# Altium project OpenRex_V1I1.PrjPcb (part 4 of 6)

## Sheet [07] - CPU - CSI, DISP.SchDoc
size A2; DocumentNumber: 7; SheetNumber: 7; SheetTotal: 31
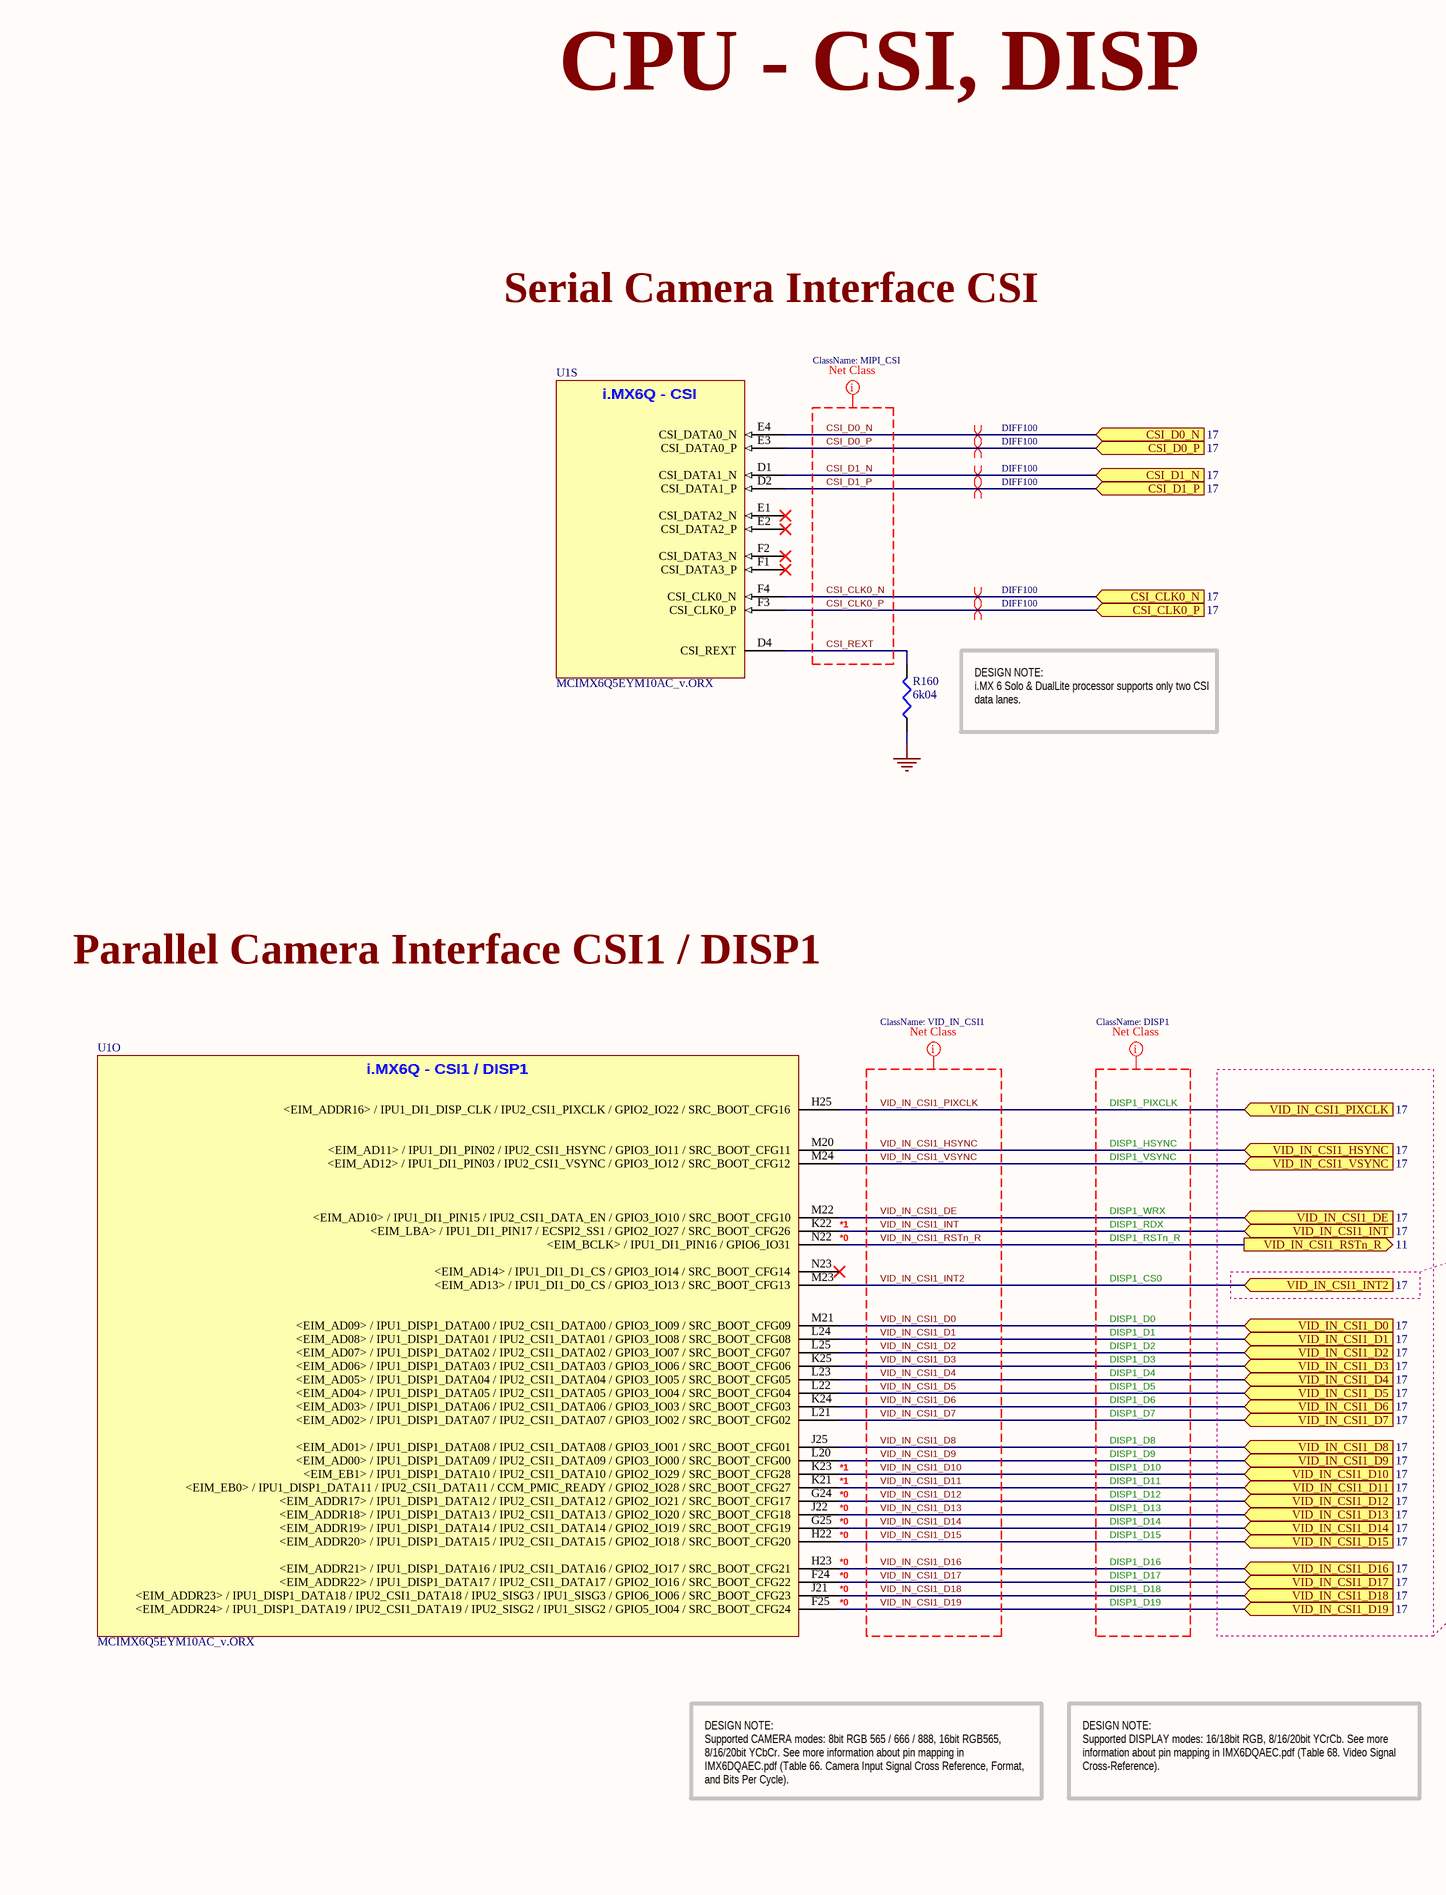
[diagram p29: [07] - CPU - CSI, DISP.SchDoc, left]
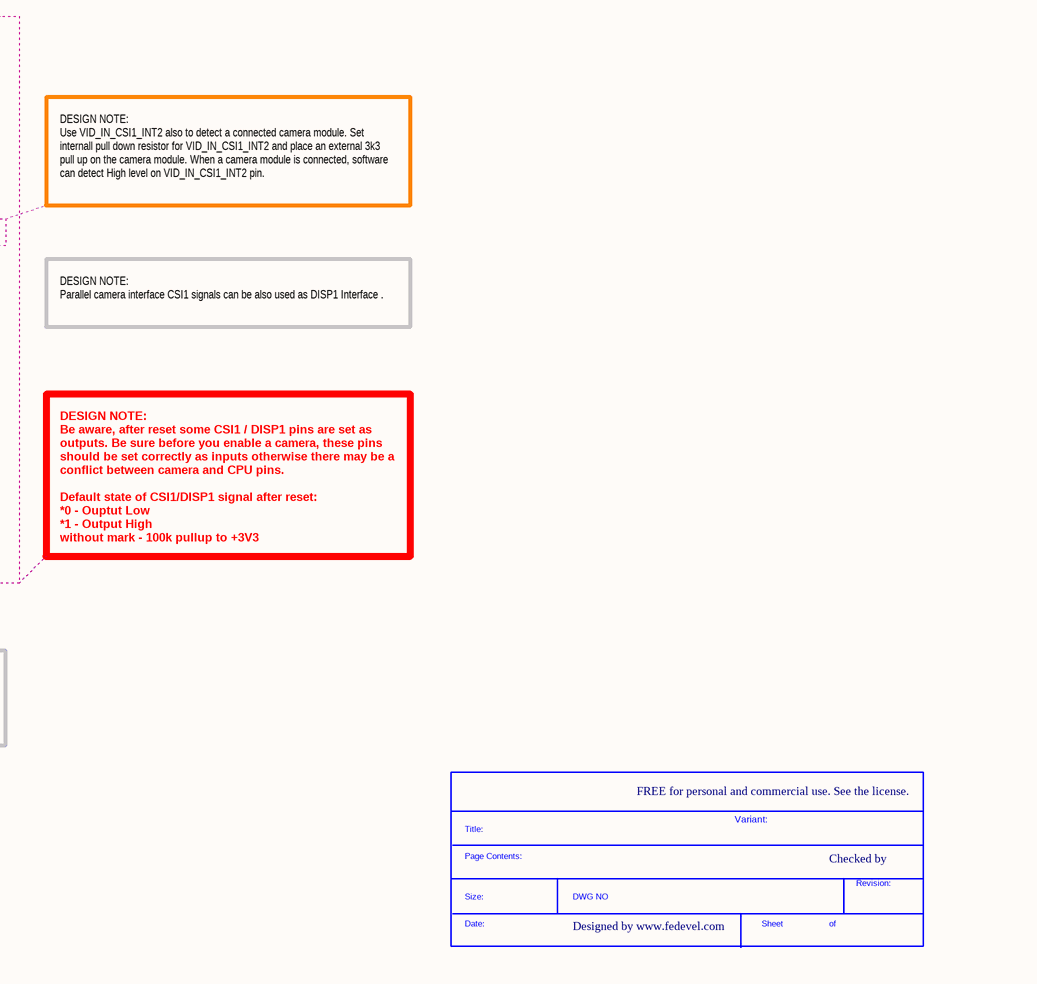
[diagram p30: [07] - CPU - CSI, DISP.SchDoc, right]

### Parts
(Parts that share a designator on the sheet are numbered #1, #2 ... from top to bottom, then left to right.)
*#18  SDTitleBlock  (value not drawn)  (graphical)
R160  6k04  [R0201]
U1  MCIMX6Q5EYM10AC_v.ORX  [PBGA624]  (parts O,S of 21)

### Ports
CSI_CLK0_N (in, see 17), CSI_CLK0_P (in, see 17), CSI_D0_N (in, see 17), CSI_D0_P (in, see 17), CSI_D1_N (in, see 17), CSI_D1_P (in, see 17), VID_IN_CSI1_D0 (in, see 17), VID_IN_CSI1_D1 (in, see 17), VID_IN_CSI1_D2 (in, see 17), VID_IN_CSI1_D3 (in, see 17), VID_IN_CSI1_D4 (in, see 17), VID_IN_CSI1_D5 (in, see 17), VID_IN_CSI1_D6 (in, see 17), VID_IN_CSI1_D7 (in, see 17), VID_IN_CSI1_D8 (in, see 17), VID_IN_CSI1_D9 (in, see 17), VID_IN_CSI1_D10 (in, see 17), VID_IN_CSI1_D11 (in, see 17), VID_IN_CSI1_D12 (in, see 17), VID_IN_CSI1_D13 (in, see 17), VID_IN_CSI1_D14 (in, see 17), VID_IN_CSI1_D15 (in, see 17), VID_IN_CSI1_D16 (in, see 17), VID_IN_CSI1_D17 (in, see 17), VID_IN_CSI1_D18 (in, see 17), VID_IN_CSI1_D19 (in, see 17), VID_IN_CSI1_DE (in, see 17), VID_IN_CSI1_HSYNC (in, see 17), VID_IN_CSI1_INT2 (in, see 17), VID_IN_CSI1_INT (in, see 17), VID_IN_CSI1_PIXCLK (in, see 17), VID_IN_CSI1_RSTn_R (out, see 11), VID_IN_CSI1_VSYNC (in, see 17)

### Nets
GND: R160.1
CSI_CLK0_N: U1.F4(CSI_CLK0_N) ; port CSI_CLK0_N
CSI_CLK0_P: U1.F3(CSI_CLK0_P) ; port CSI_CLK0_P
CSI_D0_N: U1.E4(CSI_DATA0_N) ; port CSI_D0_N
CSI_D0_P: U1.E3(CSI_DATA0_P) ; port CSI_D0_P
CSI_D1_N: U1.D1(CSI_DATA1_N) ; port CSI_D1_N
CSI_D1_P: U1.D2(CSI_DATA1_P) ; port CSI_D1_P
CSI_REXT: R160.2 U1.D4(CSI_REXT)
VID_IN_CSI1_D0: U1.M21(<EIM_AD09>_/_IPU1_DISP1_DATA00_/_IPU2_CSI1_DATA00_/_GPIO3_IO09_/_SRC_BOOT_CFG09) ; port VID_IN_CSI1_D0
VID_IN_CSI1_D1: U1.L24(<EIM_AD08>_/_IPU1_DISP1_DATA01_/_IPU2_CSI1_DATA01_/_GPIO3_IO08_/_SRC_BOOT_CFG08) ; port VID_IN_CSI1_D1
VID_IN_CSI1_D2: U1.L25(<EIM_AD07>_/_IPU1_DISP1_DATA02_/_IPU2_CSI1_DATA02_/_GPIO3_IO07_/_SRC_BOOT_CFG07) ; port VID_IN_CSI1_D2
VID_IN_CSI1_D3: U1.K25(<EIM_AD06>_/_IPU1_DISP1_DATA03_/_IPU2_CSI1_DATA03_/_GPIO3_IO06_/_SRC_BOOT_CFG06) ; port VID_IN_CSI1_D3
VID_IN_CSI1_D4: U1.L23(<EIM_AD05>_/_IPU1_DISP1_DATA04_/_IPU2_CSI1_DATA04_/_GPIO3_IO05_/_SRC_BOOT_CFG05) ; port VID_IN_CSI1_D4
VID_IN_CSI1_D5: U1.L22(<EIM_AD04>_/_IPU1_DISP1_DATA05_/_IPU2_CSI1_DATA05_/_GPIO3_IO04_/_SRC_BOOT_CFG04) ; port VID_IN_CSI1_D5
VID_IN_CSI1_D6: U1.K24(<EIM_AD03>_/_IPU1_DISP1_DATA06_/_IPU2_CSI1_DATA06_/_GPIO3_IO03_/_SRC_BOOT_CFG03) ; port VID_IN_CSI1_D6
VID_IN_CSI1_D7: U1.L21(<EIM_AD02>_/_IPU1_DISP1_DATA07_/_IPU2_CSI1_DATA07_/_GPIO3_IO02_/_SRC_BOOT_CFG02) ; port VID_IN_CSI1_D7
VID_IN_CSI1_D8: U1.J25(<EIM_AD01>_/_IPU1_DISP1_DATA08_/_IPU2_CSI1_DATA08_/_GPIO3_IO01_/_SRC_BOOT_CFG01) ; port VID_IN_CSI1_D8
VID_IN_CSI1_D9: U1.L20(<EIM_AD00>_/_IPU1_DISP1_DATA09_/_IPU2_CSI1_DATA09_/_GPIO3_IO00_/_SRC_BOOT_CFG00) ; port VID_IN_CSI1_D9
VID_IN_CSI1_D10: U1.K23(<EIM_EB1>_/_IPU1_DISP1_DATA10_/_IPU2_CSI1_DATA10_/_GPIO2_IO29_/_SRC_BOOT_CFG28) ; port VID_IN_CSI1_D10
VID_IN_CSI1_D11: U1.K21(<EIM_EB0>_/_IPU1_DISP1_DATA11_/_IPU2_CSI1_DATA11_/_CCM_PMIC_READY_/_GPIO2_IO28_/_SRC_BOOT_CFG27) ; port VID_IN_CSI1_D11
VID_IN_CSI1_D12: U1.G24(<EIM_ADDR17>_/_IPU1_DISP1_DATA12_/_IPU2_CSI1_DATA12_/_GPIO2_IO21_/_SRC_BOOT_CFG17) ; port VID_IN_CSI1_D12
VID_IN_CSI1_D13: U1.J22(<EIM_ADDR18>_/_IPU1_DISP1_DATA13_/_IPU2_CSI1_DATA13_/_GPIO2_IO20_/_SRC_BOOT_CFG18) ; port VID_IN_CSI1_D13
VID_IN_CSI1_D14: U1.G25(<EIM_ADDR19>_/_IPU1_DISP1_DATA14_/_IPU2_CSI1_DATA14_/_GPIO2_IO19_/_SRC_BOOT_CFG19) ; port VID_IN_CSI1_D14
VID_IN_CSI1_D15: U1.H22(<EIM_ADDR20>_/_IPU1_DISP1_DATA15_/_IPU2_CSI1_DATA15_/_GPIO2_IO18_/_SRC_BOOT_CFG20) ; port VID_IN_CSI1_D15
VID_IN_CSI1_D16: U1.H23(<EIM_ADDR21>_/_IPU1_DISP1_DATA16_/_IPU2_CSI1_DATA16_/_GPIO2_IO17_/_SRC_BOOT_CFG21) ; port VID_IN_CSI1_D16
VID_IN_CSI1_D17: U1.F24(<EIM_ADDR22>_/_IPU1_DISP1_DATA17_/_IPU2_CSI1_DATA17_/_GPIO2_IO16_/_SRC_BOOT_CFG22) ; port VID_IN_CSI1_D17
VID_IN_CSI1_D18: U1.J21(<EIM_ADDR23>_/_IPU1_DISP1_DATA18_/_IPU2_CSI1_DATA18_/_IPU2_SISG3_/_IPU1_SISG3_/_GPIO6_IO06_/_SRC_BOOT_CFG23) ; port VID_IN_CSI1_D18
VID_IN_CSI1_D19: U1.F25(<EIM_ADDR24>_/_IPU1_DISP1_DATA19_/_IPU2_CSI1_DATA19_/_IPU2_SISG2_/_IPU1_SISG2_/_GPIO5_IO04_/_SRC_BOOT_CFG24) ; port VID_IN_CSI1_D19
VID_IN_CSI1_DE: U1.M22(<EIM_AD10>_/_IPU1_DI1_PIN15_/_IPU2_CSI1_DATA_EN_/_GPIO3_IO10_/_SRC_BOOT_CFG10) ; port VID_IN_CSI1_DE
VID_IN_CSI1_HSYNC: U1.M20(<EIM_AD11>_/_IPU1_DI1_PIN02_/_IPU2_CSI1_HSYNC_/_GPIO3_IO11_/_SRC_BOOT_CFG11) ; port VID_IN_CSI1_HSYNC
VID_IN_CSI1_INT: U1.K22(<EIM_LBA>_/_IPU1_DI1_PIN17_/_ECSPI2_SS1_/_GPIO2_IO27_/_SRC_BOOT_CFG26) ; port VID_IN_CSI1_INT
VID_IN_CSI1_INT2: U1.M23(<EIM_AD13>_/_IPU1_DI1_D0_CS_/_GPIO3_IO13_/_SRC_BOOT_CFG13) ; port VID_IN_CSI1_INT2
VID_IN_CSI1_PIXCLK: U1.H25(<EIM_ADDR16>_/_IPU1_DI1_DISP_CLK_/_IPU2_CSI1_PIXCLK_/_GPIO2_IO22_/_SRC_BOOT_CFG16) ; port VID_IN_CSI1_PIXCLK
VID_IN_CSI1_RSTn_R: U1.N22(<EIM_BCLK>_/_IPU1_DI1_PIN16_/_GPIO6_IO31) ; port VID_IN_CSI1_RSTn_R
VID_IN_CSI1_VSYNC: U1.M24(<EIM_AD12>_/_IPU1_DI1_PIN03_/_IPU2_CSI1_VSYNC_/_GPIO3_IO12_/_SRC_BOOT_CFG12) ; port VID_IN_CSI1_VSYNC

Not connected (* = marked no-connect by the designer): U1 E1(CSI_DATA2_N)* E2(CSI_DATA2_P)* F1(CSI_DATA3_P)* F2(CSI_DATA3_N)* N23(<EIM_AD14>_/_IPU1_DI1_D1_CS_/_GPIO3_IO14_/_SRC_BOOT_CFG14)*

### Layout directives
net class DISP1: (no net found under the mark)
net class VID_IN_CSI1: VID_IN_CSI1_D0, VID_IN_CSI1_D1, VID_IN_CSI1_D2, VID_IN_CSI1_D3, VID_IN_CSI1_D4, VID_IN_CSI1_D5, VID_IN_CSI1_D6, VID_IN_CSI1_D7, VID_IN_CSI1_D8, VID_IN_CSI1_D9, VID_IN_CSI1_D10, VID_IN_CSI1_D11, VID_IN_CSI1_D12, VID_IN_CSI1_D13, VID_IN_CSI1_D14, VID_IN_CSI1_D15, VID_IN_CSI1_D16, VID_IN_CSI1_D17, VID_IN_CSI1_D18, VID_IN_CSI1_D19, VID_IN_CSI1_DE, VID_IN_CSI1_HSYNC, VID_IN_CSI1_INT, VID_IN_CSI1_INT2, VID_IN_CSI1_PIXCLK, VID_IN_CSI1_RSTn_R, VID_IN_CSI1_VSYNC
differential pair; net class DIFF100: CSI_CLK0_N, CSI_CLK0_P, CSI_D0_N, CSI_D0_P, CSI_D1_N, CSI_D1_P
net class MIPI_CSI: CSI_CLK0_N, CSI_CLK0_P, CSI_D0_N, CSI_D0_P, CSI_D1_N, CSI_D1_P, CSI_REXT

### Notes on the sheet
- CPU - CSI, DISP
- Serial Camera Interface CSI
- DESIGN NOTE:
  i.MX 6 Solo & DualLite processor supports only two CSI data lanes.
- Parallel Camera Interface CSI1 / DISP1
- DISP1_PIXCLK
- DISP1_HSYNC
- DISP1_VSYNC
- (near U1) *1
- (near U1) *0
- DISP1_RDX
- DISP1_WRX
- DISP1_RSTn_R
- DESIGN NOTE:
  Use VID_IN_CSI1_INT2 also to detect a connected camera module. Set internall pull down resistor for VID_IN_CSI1_INT2 and place an external 3k3 pull up on the camera module. When a camera module is connected, software can detect High level on VID_IN_CSI1_INT2 pin.
- DISP1_D0
- DISP1_CS0
- DISP1_D1
- DISP1_D2
- DISP1_D3
- DISP1_D4
- DISP1_D5
- DESIGN NOTE:
  Parallel camera interface CSI1 signals can be also used as DISP1 Interface .
- DISP1_D6
- DISP1_D7
- DISP1_D8
- DISP1_D9
- DISP1_D10
- DISP1_D11
- DISP1_D12
- DISP1_D13
- DISP1_D14
- DISP1_D15
- DISP1_D16
- DISP1_D17
- DISP1_D18
- DISP1_D19
- DESIGN NOTE:
  Be aware, after reset some CSI1 / DISP1 pins are set as outputs. Be sure before you enable a camera, these pins should be set correctly as inputs otherwise there may be a conflict between camera and CPU pins.
  Default state of CSI1/DISP1 signal after reset:
  *0 - Ouptut Low
  *1 - Output High
  without mark - 100k pullup to +3V3
- DESIGN NOTE:
  Supported CAMERA modes: 8bit RGB 565 / 666 / 888, 16bit RGB565, 8/16/20bit YCbCr. See more information about pin mapping in IMX6DQAEC.pdf (Table 66. Camera Input Signal Cross Reference, Format, and Bits Per Cycle).
- DESIGN NOTE:
  Supported DISPLAY modes: 16/18bit RGB, 8/16/20bit YCrCb. See more information about pin mapping in IMX6DQAEC.pdf (Table 68. Video Signal Cross-Reference).
- FREE for personal and commercial use. See the license.
- Variant:
- Checked by
- Designed by www.fedevel.com

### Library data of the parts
R160 = ERJ-1GEF6041C: RES 6.04K OHM 1/20W 1% 0201 SMD; Manufacturer: Panasonic Electronic Components; Power (Watts): 0.05W, 1/20W; Temperature Coefficient: ±200ppm/°C; .Creator: MM
U1 = MCIMX6Q5EYM10AC_v.ORX: IC MCU 32BIT ARM QUAD 624FCBGA; Manufacturer: Freescale Semiconductor; Core Processor: ARM® Cortex™-A9; Core Size: 32-Bit Quad-Core; Speed: 1.0GHz; Connectivity: CAN, EBI/EMI, ESAI, Ethernet, GPMI, I2C, MMC/SD, PCI, SATA, SPI, UART, USB, USB OTG; Peripherals: DMA, HDMI, I2S/SSI/AC97, MIPI CSI, MIMI DSI, MIPI HIS, PWM, WDT; Number of I /O: 224; Program Memory Type: External Program Memory; RAM Size: 256K x 8; Voltage - Supply (Vcc/Vdd): 0.925 V ~ 1.5 V; Oscillator Type: Internal; .Creator: MM; .Checked PCB: MM, checked by RF

## Sheet [14] - MCU.SchDoc
size A2; DocumentNumber: 14; SheetNumber: 14; SheetTotal: 31
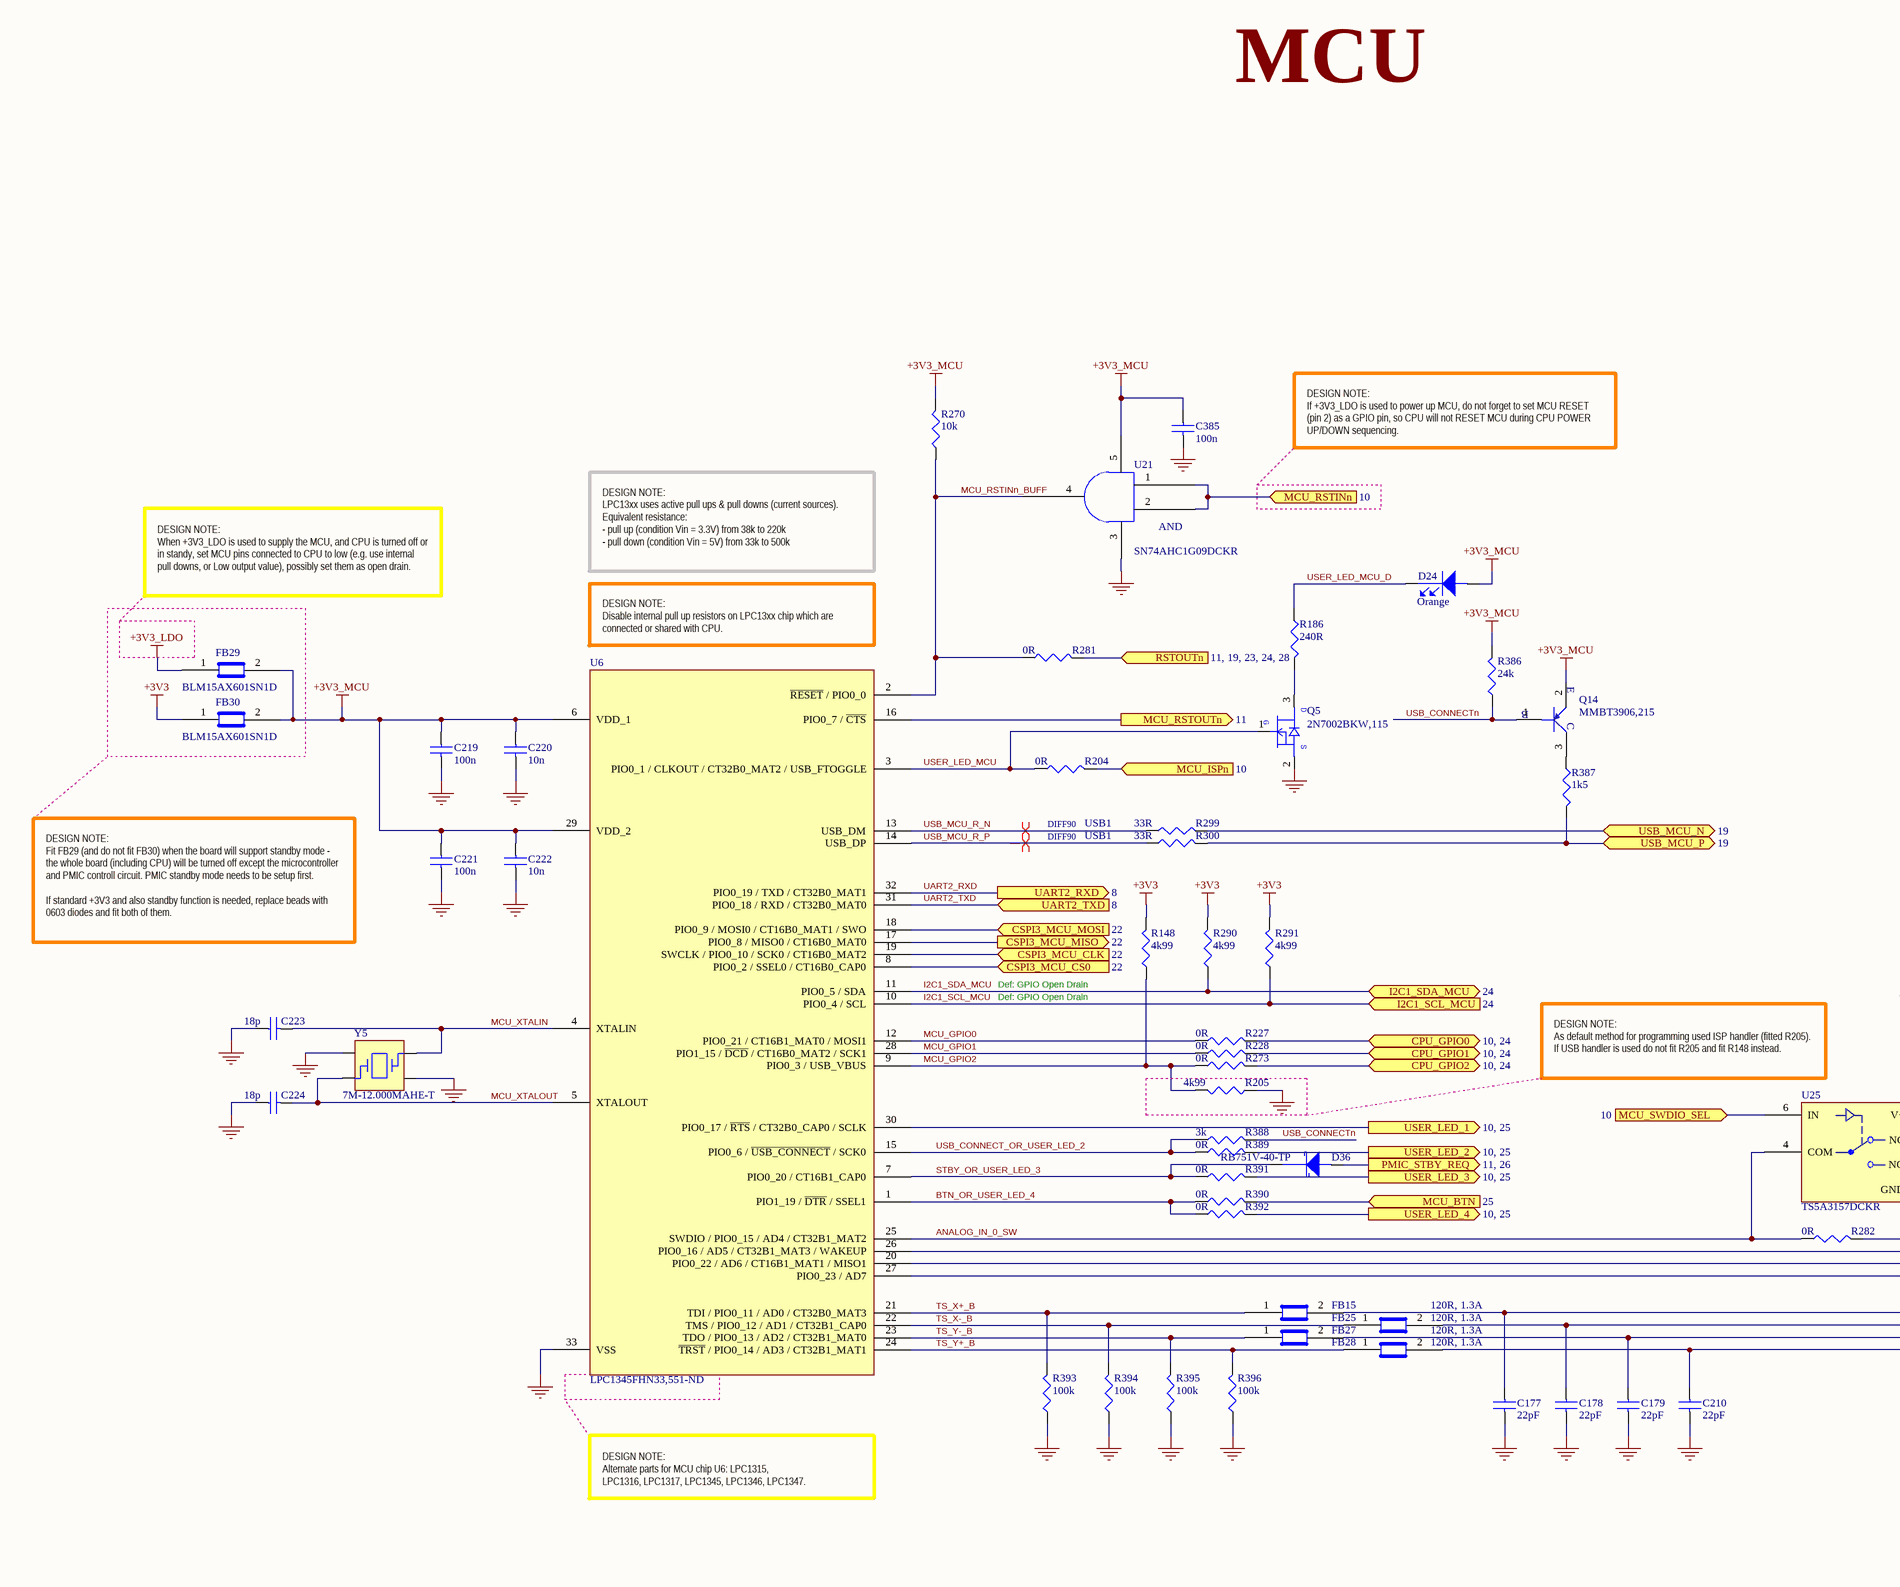
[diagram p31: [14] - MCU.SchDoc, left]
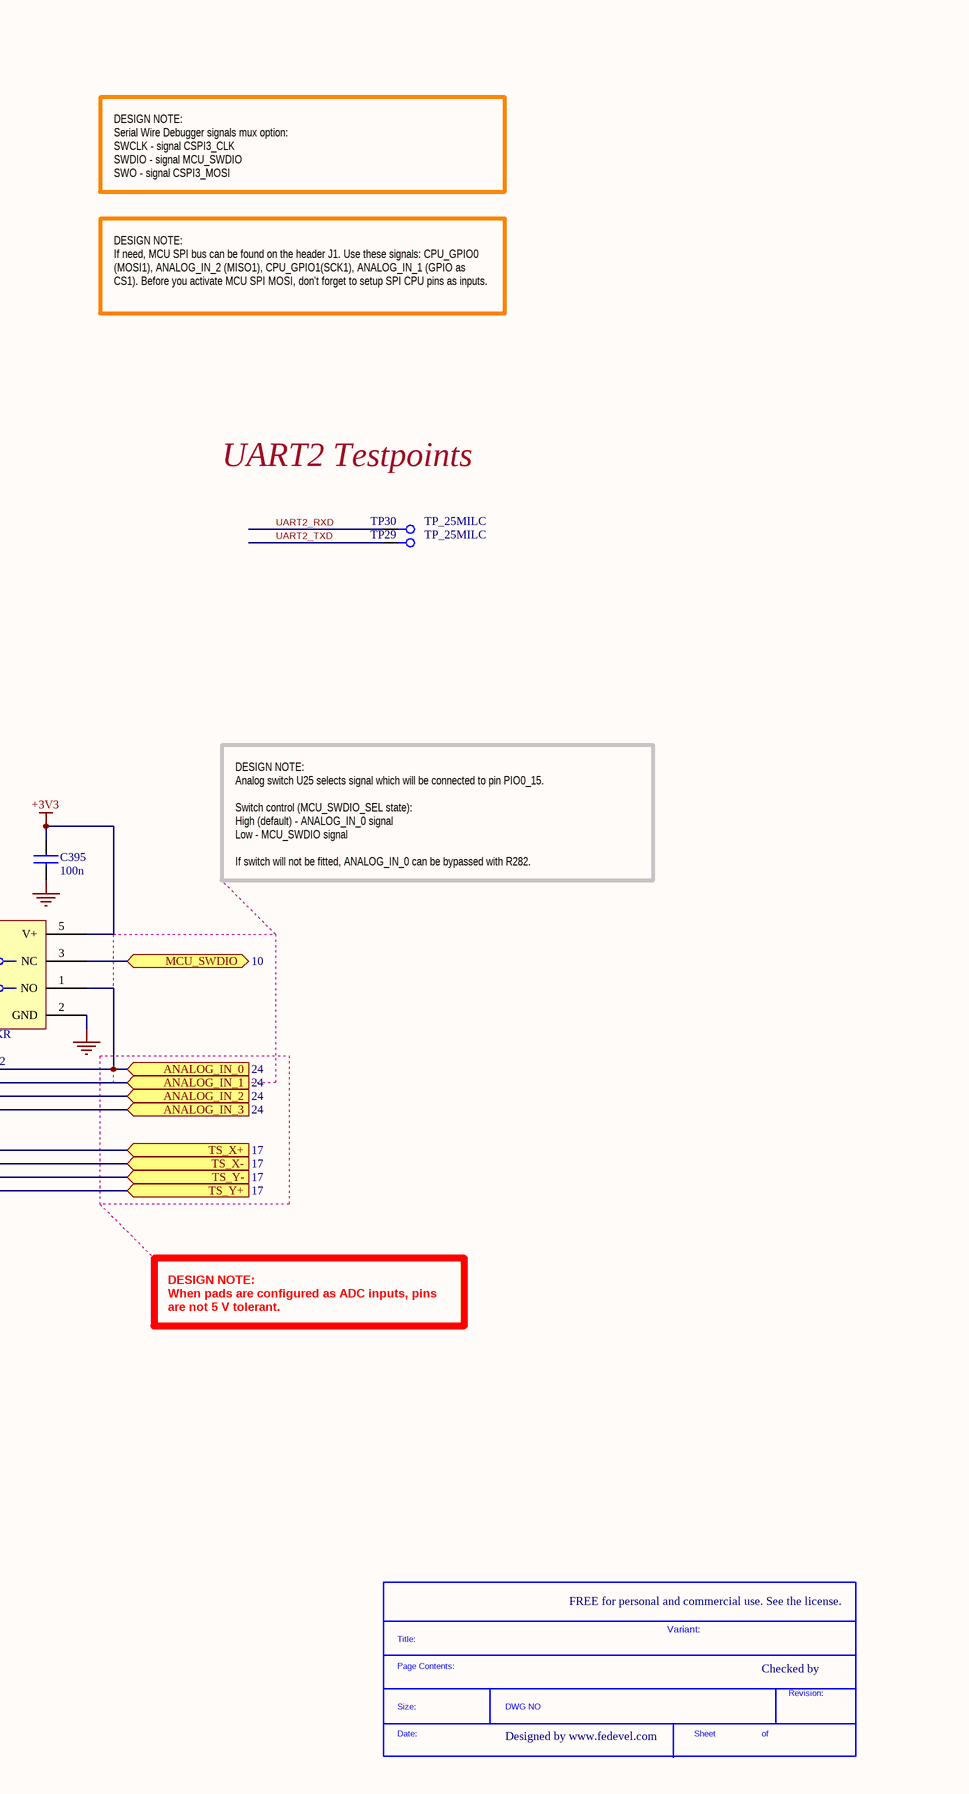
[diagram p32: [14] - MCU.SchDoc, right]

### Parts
(Parts that share a designator on the sheet are numbered #1, #2 ... from top to bottom, then left to right.)
*#19  SDTitleBlock  (value not drawn)  (graphical)
C177  22pF  [C0402]
C178  22pF  [C0402]
C179  22pF  [C0402]
C210  22pF  [C0402]
C219  100n  [C0402]
C220  10n  [C0402]
C221  100n  [C0402]
C222  10n  [C0402]
C223  18p  [C0402]
C224  18p  [C0402]
C385  100n  [C0402]
C395  100n  [C0402]
D24  Orange  [LED_0603]
D36  RB751V-40-TP  [SOD323]
FB15  120R, 1.3A  [C0402]
FB25  120R, 1.3A  [C0402]
FB27  120R, 1.3A  [C0402]
FB28  120R, 1.3A  [C0402]
FB29  BLM15AX601SN1D  [C0402]
FB30  BLM15AX601SN1D  [C0402]
Q5  2N7002BKW,115  [SC70_SOT323]
Q14  MMBT3906,215  [SOT-23-3-123]
R148  4k99  [R0402]
R186  240R  [R0402]
R204  0R  [R0402]
R205  4k99  [R0402]
R227  0R  [R0402]
R228  0R  [R0402]
R270  10k  [R0402]
R273  0R  [R0402]
R281  0R  [R0402]
R282  0R  [R0402]
R290  4k99  [R0402]
R291  4k99  [R0402]
R299  33R  [R0402]
R300  33R  [R0402]
R386  24k  [R0402]
R387  1k5  [R0402]
R388  3k  [R0402]
R389  0R  [R0402]
R390  0R  [R0402]
R391  0R  [R0402]
R392  0R  [R0402]
R393  100k  [R0402]
R394  100k  [R0402]
R395  100k  [R0402]
R396  100k  [R0402]
TP29  TP_25MILC  [TP_25C]  (no BOM)
TP30  TP_25MILC  [TP_25C]  (no BOM)
U6  LPC1345FHN33,551-ND  [HVQFN33_7x7mm]
U21  SN74AHC1G09DCKR  [SC70_5]
U25  TS5A3157DCKR  [SC70_6]
Y5  7M-12.000MAHE-T  [7M]

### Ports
ANALOG_IN_0 (in, see 24), ANALOG_IN_1 (in, see 24), ANALOG_IN_2 (in, see 24), ANALOG_IN_3 (in, see 24), CPU_GPIO0 (bidir, see 10, 24), CPU_GPIO1 (bidir, see 10, 24), CPU_GPIO2 (bidir, see 10, 24), CSPI3_MCU_CLK (in, see 22), CSPI3_MCU_CS0 (in, see 22), CSPI3_MCU_MISO (out, see 22), CSPI3_MCU_MOSI (in, see 22), I2C1_SCL_MCU (in, see 24), I2C1_SDA_MCU (bidir, see 24), MCU_BTN (in, see 25), MCU_ISPn (in, see 10), MCU_RSTINn (in, see 10), MCU_RSTOUTn (out, see 11), MCU_SWDIO (bidir, see 10), MCU_SWDIO_SEL (in, see 10), PMIC_STBY_REQ (out, see 11, 26), RSTOUTn (see 11, 19, 23, 24, 28), TS_X+ (in, see 17), TS_X- (in, see 17), TS_Y+ (in, see 17), TS_Y- (in, see 17), UART2_RXD (out, see 8), UART2_TXD (in, see 8), USB_MCU_N (bidir, see 19), USB_MCU_P (bidir, see 19), USER_LED_1 (out, see 10, 25), USER_LED_2 (out, see 10, 25), USER_LED_3 (out, see 10, 25), USER_LED_4 (out, see 10, 25)

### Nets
+3V3: C395.1 FB30.1 R148.2 R290.2 R291.2 U25.5(V+)
+3V3_LDO: FB29.1
+3V3_MCU: C219.1 C220.1 C221.1 C222.1 C385.1 D24.2(ANODE) FB29.2 FB30.2 Q14.2(E) R270.2 R386.2 U6.6(VDD_1) U6.29(VDD_2) U21.5(VCC)
GND: C177.2 C178.2 C179.2 C210.2 C219.2 C220.2 C221.2 C222.2 C223.1 C224.1 C385.2 C395.2 Q5.2(SOURCE) R205.1 R393.1 R394.1 R395.1 R396.1 U6.33(VSS) U21.3(GND) U25.2(GND) Y5.2 Y5.4
ANALOG_IN_0: R282.2 U25.1(NO) ; port ANALOG_IN_0
ANALOG_IN_0_SW: R282.1 U6.25(SWDIO_/_PIO0_15_/_AD4_/_CT32B1_MAT2) U25.4(COM)
ANALOG_IN_1: U6.26(PIO0_16_/_AD5_/_CT32B1_MAT3_/_WAKEUP) ; port ANALOG_IN_1
ANALOG_IN_2: U6.20(PIO0_22_/_AD6_/_CT16B1_MAT1_/_MISO1) ; port ANALOG_IN_2
ANALOG_IN_3: U6.27(PIO0_23_/_AD7) ; port ANALOG_IN_3
BTN_OR_USER_LED_4: R390.1 R392.1 U6.1(PIO1_19_/_~{DTR}_/_SSEL1)
CPU_GPIO0: R227.2 ; port CPU_GPIO0
CPU_GPIO1: R228.2 ; port CPU_GPIO1
CPU_GPIO2: R273.2 ; port CPU_GPIO2
CSPI3_MCU_CLK: U6.19(SWCLK_/_PIO0_10_/_SCK0_/_CT16B0_MAT2) ; port CSPI3_MCU_CLK
CSPI3_MCU_CS0: U6.8(PIO0_2_/_SSEL0_/_CT16B0_CAP0) ; port CSPI3_MCU_CS0
CSPI3_MCU_MISO: U6.17(PIO0_8_/_MISO0_/_CT16B0_MAT0) ; port CSPI3_MCU_MISO
CSPI3_MCU_MOSI: U6.18(PIO0_9_/_MOSI0_/_CT16B0_MAT1_/_SWO) ; port CSPI3_MCU_MOSI
I2C1_SCL_MCU: R291.1 U6.10(PIO0_4_/_SCL) ; port I2C1_SCL_MCU
I2C1_SDA_MCU: R290.1 U6.11(PIO0_5_/_SDA) ; port I2C1_SDA_MCU
MCU_BTN: R390.2 ; port MCU_BTN
MCU_GPIO0: R227.1 U6.12(PIO0_21_/_CT16B1_MAT0_/_MOSI1)
MCU_GPIO1: R228.1 U6.28(PIO1_15_/_~{DCD}_/_CT16B0_MAT2_/_SCK1)
MCU_GPIO2: R148.1 R205.2 R273.1 U6.9(PIO0_3_/_USB_VBUS)
MCU_ISPn: R204.2 ; port MCU_ISPn
MCU_RSTINn: U21.1(A) U21.2(B) ; port MCU_RSTINn
MCU_RSTINn_BUFF: R270.1 R281.1 U6.2(~{RESET}_/_PIO0_0) U21.4(Y)
MCU_RSTOUTn: U6.16(PIO0_7_/_~{CTS}) ; port MCU_RSTOUTn
MCU_SWDIO: U25.3(NC) ; port MCU_SWDIO
MCU_SWDIO_SEL: U25.6(IN) ; port MCU_SWDIO_SEL
MCU_XTALIN: C223.2 U6.4(XTALIN) Y5.1
MCU_XTALOUT: C224.2 U6.5(XTALOUT) Y5.3
PMIC_STBY_REQ: D36.2(ANODE) ; port PMIC_STBY_REQ
RSTOUTn: R281.2 ; port RSTOUTn
STBY_OR_USER_LED_3: D36.1(cathode) R391.1 U6.7(PIO0_20_/_CT16B1_CAP0)
TS_X+: C177.1 FB15.2 ; port TS_X+
TS_X+_B: FB15.1 R393.2 U6.21(TDI_/_PIO0_11_/_AD0_/_CT32B0_MAT3)
TS_X-: C178.1 FB25.2 ; port TS_X-
TS_X-_B: FB25.1 R394.2 U6.22(TMS_/_PIO0_12_/_AD1_/_CT32B1_CAP0)
TS_Y+: C210.1 FB28.2 ; port TS_Y+
TS_Y+_B: FB28.1 R396.2 U6.24(~{TRST}_/_PIO0_14_/_AD3_/_CT32B1_MAT1)
TS_Y-: C179.1 FB27.2 ; port TS_Y-
TS_Y-_B: FB27.1 R395.2 U6.23(TDO_/_PIO0_13_/_AD2_/_CT32B1_MAT0)
UART2_RXD: TP30.1 U6.32(PIO0_19_/_TXD_/_CT32B0_MAT1) ; port UART2_RXD
UART2_TXD: TP29.1 U6.31(PIO0_18_/_RXD_/_CT32B0_MAT0) ; port UART2_TXD
USB_CONNECT_OR_USER_LED_2: R388.1 R389.1 U6.15(PIO0_6_/_~{USB_CONNECT}_/_SCK0)
USB_CONNECTn: Q14.1(B) R386.1 R388.2
USB_MCU_N: R299.2 ; port USB_MCU_N
USB_MCU_P: R300.2 R387.2 ; port USB_MCU_P
USB_MCU_R_N: R299.1 U6.13(USB_DM)
USB_MCU_R_P: R300.1 U6.14(USB_DP)
USER_LED_1: U6.30(PIO0_17_/_~{RTS}_/_CT32B0_CAP0_/_SCLK) ; port USER_LED_1
USER_LED_2: R389.2 ; port USER_LED_2
USER_LED_3: R391.2 ; port USER_LED_3
USER_LED_4: R392.2 ; port USER_LED_4
USER_LED_MCU: Q5.1(GATE) R204.1 U6.3(PIO0_1_/_CLKOUT_/_CT32B0_MAT2_/_USB_FTOGGLE)
USER_LED_MCU_D: D24.1(cathode) R186.1
NetQ5_3: Q5.3(DRAIN) R186.2
NetQ14_3: Q14.3(C) R387.1

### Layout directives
differential pair; net class DIFF90; net class USB1: USB_MCU_R_N, USB_MCU_R_P

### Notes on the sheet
- MCU
- DESIGN NOTE:
  If +3V3_LDO is used to power up MCU, do not forget to set MCU RESET (pin 2) as a GPIO pin, so CPU will not RESET MCU during CPU POWER UP/DOWN sequencing.
- DESIGN NOTE:
  Serial Wire Debugger signals mux option:
  SWCLK - signal CSPI3_CLK
  SWDIO - signal MCU_SWDIO
  SWO - signal CSPI3_MOSI
- DESIGN NOTE:
  LPC13xx uses active pull ups & pull downs (current sources).
  Equivalent resistance:
  - pull up (condition Vin = 3.3V) from 38k to 220k
  - pull down (condition Vin = 5V) from 33k to 500k
- DESIGN NOTE:
  If need, MCU SPI bus can be found on the header J1. Use these signals: CPU_GPIO0 (MOSI1), ANALOG_IN_2 (MISO1), CPU_GPIO1(SCK1), ANALOG_IN_1 (GPIO as CS1). Before you activate MCU SPI MOSI, don't forget to setup SPI CPU pins as inputs.
- DESIGN NOTE:
  When +3V3_LDO is used to supply the MCU, and CPU is turned off or in standy, set MCU pins connected to CPU to low (e.g. use internal pull downs, or Low output value), possibly set them as open drain.
- DESIGN NOTE:
  Disable internal pull up resistors on LPC13xx chip which are connected or shared with CPU.
- UART2 Testpoints
- DESIGN NOTE:
  Fit FB29 (and do not fit FB30) when the board will support standby mode - the whole board (including CPU) will be turned off except the microcontroller and PMIC controll circuit. PMIC standby mode needs to be setup first.
  If standard +3V3 and also standby function is needed, replace beads with 0603 diodes and fit both of them.
- Def: GPIO Open Drain
- DESIGN NOTE:
  Analog switch U25 selects signal which will be connected to pin PIO0_15.
  Switch control (MCU_SWDIO_SEL state):
  High (default) - ANALOG_IN_0 signal
  Low - MCU_SWDIO signal
  If switch will not be fitted, ANALOG_IN_0 can be bypassed with R282.
- (near U25) DESIGN NOTE:
  As default method for programming used ISP handler (fitted R205). If USB handler is used do not fit R205 and fit R148 instead.
- DESIGN NOTE:
  Alternate parts for MCU chip U6: LPC1315,
  LPC1316, LPC1317, LPC1345, LPC1346, LPC1347.
- DESIGN NOTE:
  When pads are configured as ADC inputs, pins are not 5 V tolerant.
- FREE for personal and commercial use. See the license.
- Variant:
- Checked by
- Designed by www.fedevel.com

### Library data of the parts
C177-C179 C210 = C1005C0G1H220J: CAP CER 22PF 50V C0G 5% 0402; Manufacturer: TDK Corporation; .Checked PCB: used; Temperature Coefficient: C0G, NP0
C219 C221 C385 C395 = C1005X5R1H104K: CAP CER .10UF 50V X5R 10% 0402; Manufacturer: TDK Corporation; Capacitance: 0.1µF; Value: 100nF; .Checked PCB: used
C220 C222 = C1005X7R1H103K: CAP CER 10000PF 50V 10% X7R 0402; Manufacturer: TDK Corporation; Value: 10nF; .Checked PCB: used
C223 C224 = C1005C0G1H180J: CAP CER 18PF 50V C0G 5% 0402; Manufacturer: TDK Corporation; .Checked PCB: used; Temperature Coefficient: C0G, NP0
D24 = LO L29K-H2K1-24-Z: LED SMARTLED ORANGE 606NM 0603; Manufacturer: OSRAM Opto Semiconductors Inc; Millicandela Rating: 6.3mcd; Voltage - Forward (Vf) Typ: 1.8V; Current - Test: 2mA; Wavelength - Peak: 610nm; Viewing Angle: 160°; Lens Type: Diffused; Lens Style/Size: Rectangle with Flat Top, 1.3mm x 0.8mm; Luminous Flux @ Current - Test: 25 mlm; .Checked PCB: used
D36 = RB751V-40-TP: DIODE SCHTKY 30MA 30V SOD-323; Manufacturer: Micro Commercial Co; Diode Type: Schottky; Voltage - Forward (Vf) (Max) @ If: 370mV @ 1mA; Speed: Small Signal =< 200mA (Io), Any Speed; Current - Reverse Leakage @ Vr: 500nA @ 30V; Capacitance @ Vr, F: 2pF @ 1V, 1MHz; .Checked PCB: used
FB15 FB25 FB27 FB28 = BLM15PD121SN1D: FERRITE CHIP 120 OHM 1300MA 0402; Manufacturer: Murata Electronics North America; Impedance @ Frequency: 120 Ohm @ 100MHz; DC Resistance (DCR): 90 mOhm Max; Filter Type: Differential Mode - Single; .Checked PCB: MM
FB29 FB30 = BLM15AX601SN1D: FERRITE CHIP 600 OHM 0402 420mA; Manufacturer: Murata Electronics North America; .Checked PCB: used; Impedance @ Frequency: 600 Ohm @ 100MHz; DC Resistance (DCR): 340 mOhm Max; Filter Type: Differential Mode - Single; Number of Lines: 1
Q5 = 2N7002BKW,115: MOSFET N-CH 60V 310MA SOT323; Manufacturer: NXP Semiconductors; FET Type: MOSFET N-Channel, Metal Oxide; FET Feature: Logic Level Gate; Rds On (Max) @ Id, Vgs: 1.6 Ohm @ 500mA, 10V; Vgs(th) (Max) @ Id: 2.1V @ 250µA; Gate Charge (Qg) @ Vgs: 0.6nC @ 4.5V; Input Capacitance (Ciss) @ Vds: 50pF @ 10V; Power - Max: 275mW; .Checked PCB: used
Q14 = MMBT3906,215: TRANS PNP 40V 0.2A SOT23; Manufacturer: NXP Semiconductors; Current - Collector (Ic) (Max): 200mA; Vce Saturation (Max) @ Ib, Ic: 400mV @ 5mA, 50mA; DC Current Gain (hFE) (Min) @ Ic, Vce: 100 @ 10mA, 1V; Power - Max: 250mW; Frequency - Transition: 250MHz; .Checked PCB: MM
R148 R205 R290 R291 = RMCF0402FT4K99: RES TF 4.99K OHM 1% 1/16W 0402; Manufacturer: Stackpole Electronics Inc; Power (Watts): 0.063W, 1/16W; .Checked PCB: used; Temperature Coefficient: ±100ppm/°C
R186 = RMCF0402FT240R: RES TF 240 OHM 1% 0.0625W 0402; Manufacturer: Stackpole Electronics Inc; Resistance (Ohms): 240; Power (Watts): 0.063W, 1/16W; .Checked PCB: used; Temperature Coefficient: ±100ppm/°C
R204 R227 R228 R273 R281 R282 R389-R392 = RC0402JR-070RL: RES 0.0 OHM 1/16W 0402 SMD; Manufacturer: Yageo; Resistance (Ohms): 0.0; Power (Watts): 0.063W, 1/16W; Tolerance: Jumper; .Checked PCB: used
R270 = RC0402FR-0710KL: RES 10.0K OHM 1/16W 1% 0402 SMD; Manufacturer: Yageo; Power (Watts): 0.063W, 1/16W; .Checked PCB: used; Temperature Coefficient: ±100ppm/°C
R299 R300 = RMCF0402FT33R0: RES TF 33 OHM 1% 1/16W 0402; Manufacturer: Stackpole Electronics Inc; Resistance (Ohms): 33; Power (Watts): 0.063W, 1/16W; .Checked PCB: used; Temperature Coefficient: ±100ppm/°C
R386 = RC0402FR-0724KL: RES SMD 24K OHM 1% 1/16W 0402; Manufacturer: Yageo; Power (Watts): 0.063W, 1/16W; Temperature Coefficient: ±100ppm/°C; .Creator: MM
R387 = RC0402FR-071K5L: RES 1.50K OHM 1/16W 1% 0402 SMD; Manufacturer: Yageo; Resistance (Ohms): 1.5k; Power (Watts): 0.063W, 1/16W; Temperature Coefficient: ±100ppm/°C; .Creator: MM
R388 = RC0402FR-073KL: RES 3K OHM 1/16W 1% 0402 SMD; Manufacturer: Yageo; Power (Watts): 0.063W, 1/16W; Temperature Coefficient: ±100ppm/°C; .Creator: MM; .Checked SCH: used
R393-R396 = RMCF0402FT100K: RES 100K OHM 1/16W 1% 0402 SMD; Manufacturer: Stackpole Electronics Inc; Power (Watts): 0.063W, 1/16W; .Checked PCB: used; Temperature Coefficient: ±100ppm/°C
TP29 TP30 = TP_25MILC: Test Point 25mil
U6 = LPC1345FHN33,551: IC MCU ARM 32KB FLASH 32HVQFN; Manufacturer: NXP Semiconductors; Core Processor: ARM® Cortex®-M3; Core Size: 32-Bit; Speed: 72MHz; Connectivity: I²C, Microwire, SPI, SSI, SSP, UART/USART, USB; Peripherals: Brown-out Detect/Reset, POR, WDT; Number of I/O: 26; Program Memory Size: 32KB (32K x 8); EEPROM Size: 2K x 8; RAM Size: 10K x 8; Voltage - Supply (Vcc/Vdd): 2 V ~ 3.6 V; Data Converters: A/D 8x12b; Oscillator Type: Internal; .Checked PCB: MM
U21 = SN74AHC1G09DCKR: IC GATE AND 1CH 2-INP SC-70-5; Manufacturer: Texas Instruments; Logic Type: AND Gate; Number of Circuits: 1; Number of Inputs: 2; Voltage - Supply: 2 V ~ 5.5 V; Current - Quiescent (Max): 1µA; Current - Output High, Low: -, 8mA; Logic Level - Low: 0.5 V ~ 1.65 V; Logic Level - High: 1.5 V ~ 3.85 V; Max Propagation Delay @ V, Max CL: 7.5ns @ 5V, 50pF; .Creator: MM; .Checked PCB: RF, used by MM
U25 = TS5A3157DCKR: IC SWITCH SPDT SC70-6; Manufacturer: Texas Instruments; Circuit: 1 x SPDT; On-State Resistance: 10 Ohm; Voltage Supply Source: Single Supply; Voltage - Supply, Single/Dual (±): 1.65 V ~ 5.5 V; Current - Supply: 2.5µA; .Checked PCB: MM
Y5 = 7M-12.000MAHE-T: CRYSTAL 12MHZ 12PF SMD; Manufacturer: TXC CORPORATION; Frequency Stability: ±30ppm; ESR (Equivalent Series Resistance): 100 Ohm; Operating Mode: Fundamental; .Creator: MM

## Sheet [20] - ETHERNET, SATA.SchDoc
size A3; DocumentNumber: 20; SheetNumber: 20; SheetTotal: 31
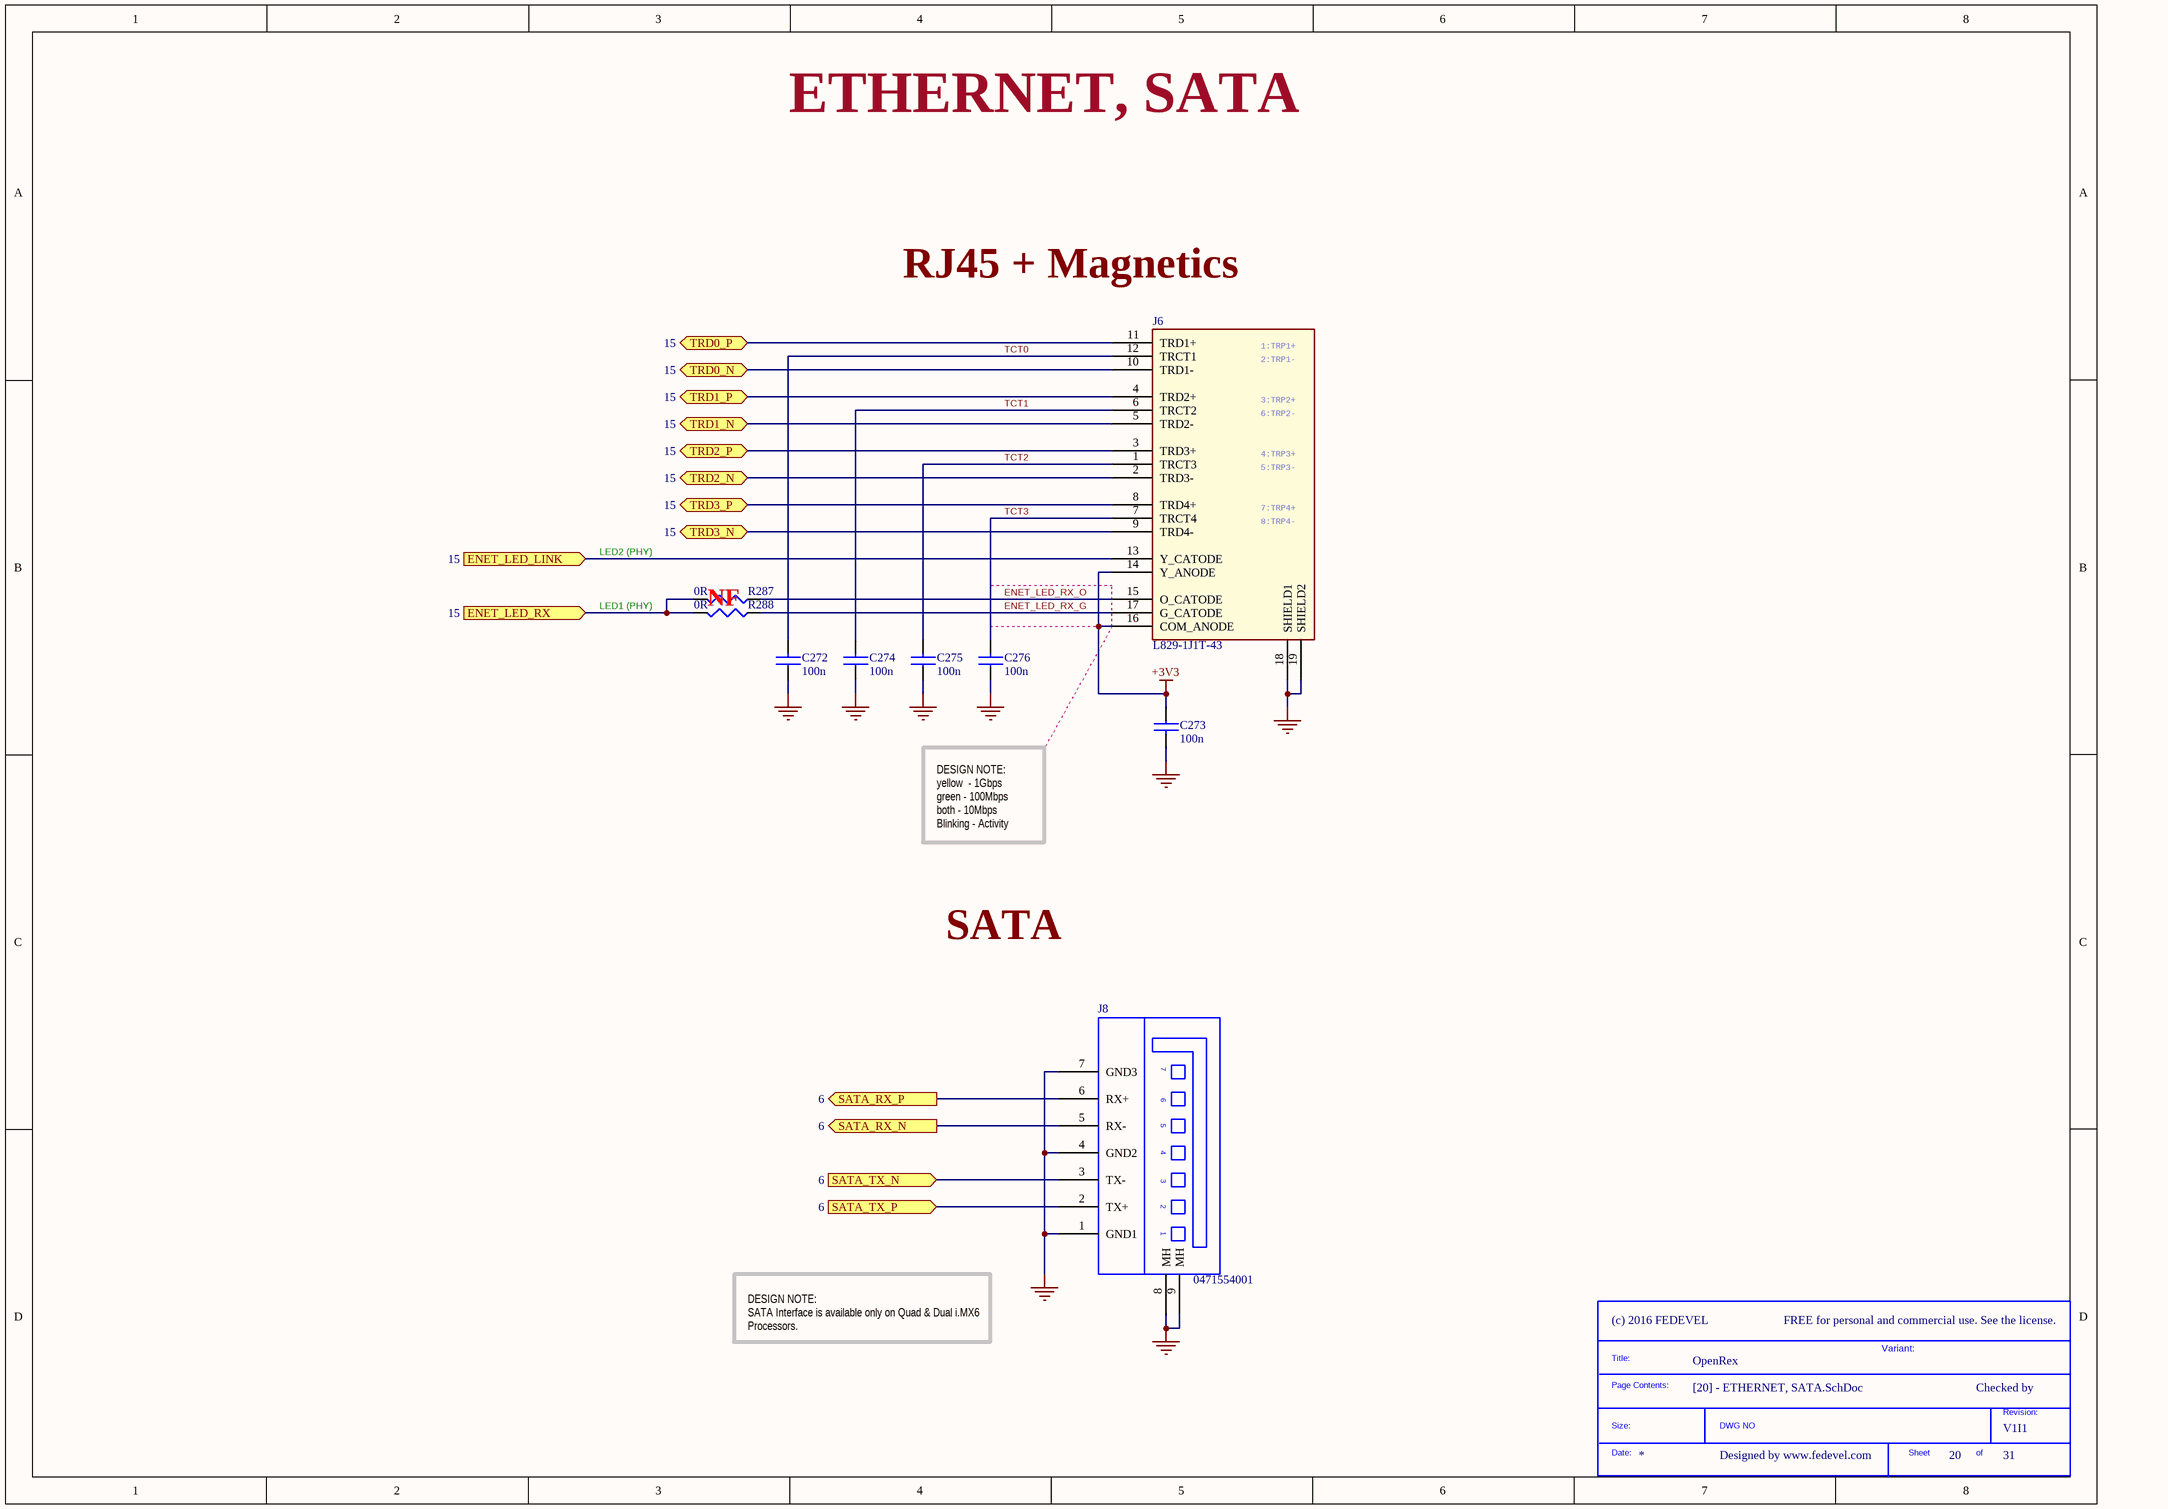
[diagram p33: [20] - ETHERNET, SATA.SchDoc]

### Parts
(Parts that share a designator on the sheet are numbered #1, #2 ... from top to bottom, then left to right.)
*#20  SDTitleBlock  (value not drawn)  (graphical)
C272  100n  [C0402]
C273  100n  [C0402]
C274  100n  [C0402]
C275  100n  [C0402]
C276  100n  [C0402]
J6  L829-1J1T-43  [L829-1J1T-43]
J8  0471554001  [SATA_VERTICAL]
R287  0R  [R0402]
R288  0R  [R0402]

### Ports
ENET_LED_LINK (in, see 15), ENET_LED_RX (in, see 15), SATA_RX_N (out, see 6), SATA_RX_P (out, see 6), SATA_TX_N (in, see 6), SATA_TX_P (in, see 6), TRD0_N (bidir, see 15), TRD0_P (bidir, see 15), TRD1_N (bidir, see 15), TRD1_P (bidir, see 15), TRD2_N (bidir, see 15), TRD2_P (bidir, see 15), TRD3_N (bidir, see 15), TRD3_P (bidir, see 15)

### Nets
+3V3: C273.1 J6.14(Y_ANODE) J6.16(COM_ANODE)
GND: C272.1 C273.2 C274.1 C275.1 C276.1 J6.18(SHIELD1) J6.19(SHIELD2) J8.1(GND1) J8.4(GND2) J8.7(GND3) J8.8(MH) J8.9(MH)
ENET_LED_LINK: J6.13(Y_CATODE) ; port ENET_LED_LINK
ENET_LED_RX: R287.2 R288.2 ; port ENET_LED_RX
ENET_LED_RX_G: J6.17(G_CATODE) R288.1
ENET_LED_RX_O: J6.15(O_CATODE) R287.1
SATA_RX_N: J8.5(RX-) ; port SATA_RX_N
SATA_RX_P: J8.6(RX+) ; port SATA_RX_P
SATA_TX_N: J8.3(TX-) ; port SATA_TX_N
SATA_TX_P: J8.2(TX+) ; port SATA_TX_P
TCT0: C272.2 J6.12(TRCT1)
TCT1: C274.2 J6.6(TRCT2)
TCT2: C275.2 J6.1(TRCT3)
TCT3: C276.2 J6.7(TRCT4)
TRD0_N: J6.10(TRD1-) ; port TRD0_N
TRD0_P: J6.11(TRD1+) ; port TRD0_P
TRD1_N: J6.5(TRD2-) ; port TRD1_N
TRD1_P: J6.4(TRD2+) ; port TRD1_P
TRD2_N: J6.2(TRD3-) ; port TRD2_N
TRD2_P: J6.3(TRD3+) ; port TRD2_P
TRD3_N: J6.9(TRD4-) ; port TRD3_N
TRD3_P: J6.8(TRD4+) ; port TRD3_P

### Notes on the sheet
- ETHERNET, SATA
- RJ45 + Magnetics
- LED2 (PHY)
- LED1 (PHY)
- DESIGN NOTE:
  yellow  - 1Gbps
  green - 100Mbps
  both - 10Mbps
  Blinking - Activity
- SATA
- FREE for personal and commercial use. See the license.
- DESIGN NOTE:
  SATA Interface is available only on Quad & Dual i.MX6 Processors.
- Variant:
- Checked by
- Designed by www.fedevel.com

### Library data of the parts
C272-C276 = C1005X5R1H104K: as C219 on sheet [14] - MCU
J6 = L829-1J1T-43: CONN MAGJACK 1PORT SHLD 1000BT; Manufacturer: Bel Fuse Inc; Connector Type: RJ45; Number of Ports: 1; Speed: 10/100/1000 Base-T; LED Color: Green, Orange - Yellow; Number of Cores per Jack: 8; Shielding: Shielded; Tab Direction: Up; .Checked PCB: RF
J8 = 0471554001: CONN SATA HDR 7POS PCB VERT; Manufacturer: Molex Inc; Connector Style: Header, Shrouded; Number of Positions: 7; .Checked PCB: used
R287 R288 = RC0402JR-070RL: as R204 on sheet [14] - MCU

## Sheet [25] - LEDS, BUTTONS.SchDoc
size A2; DocumentNumber: 25; SheetNumber: 25; SheetTotal: 31
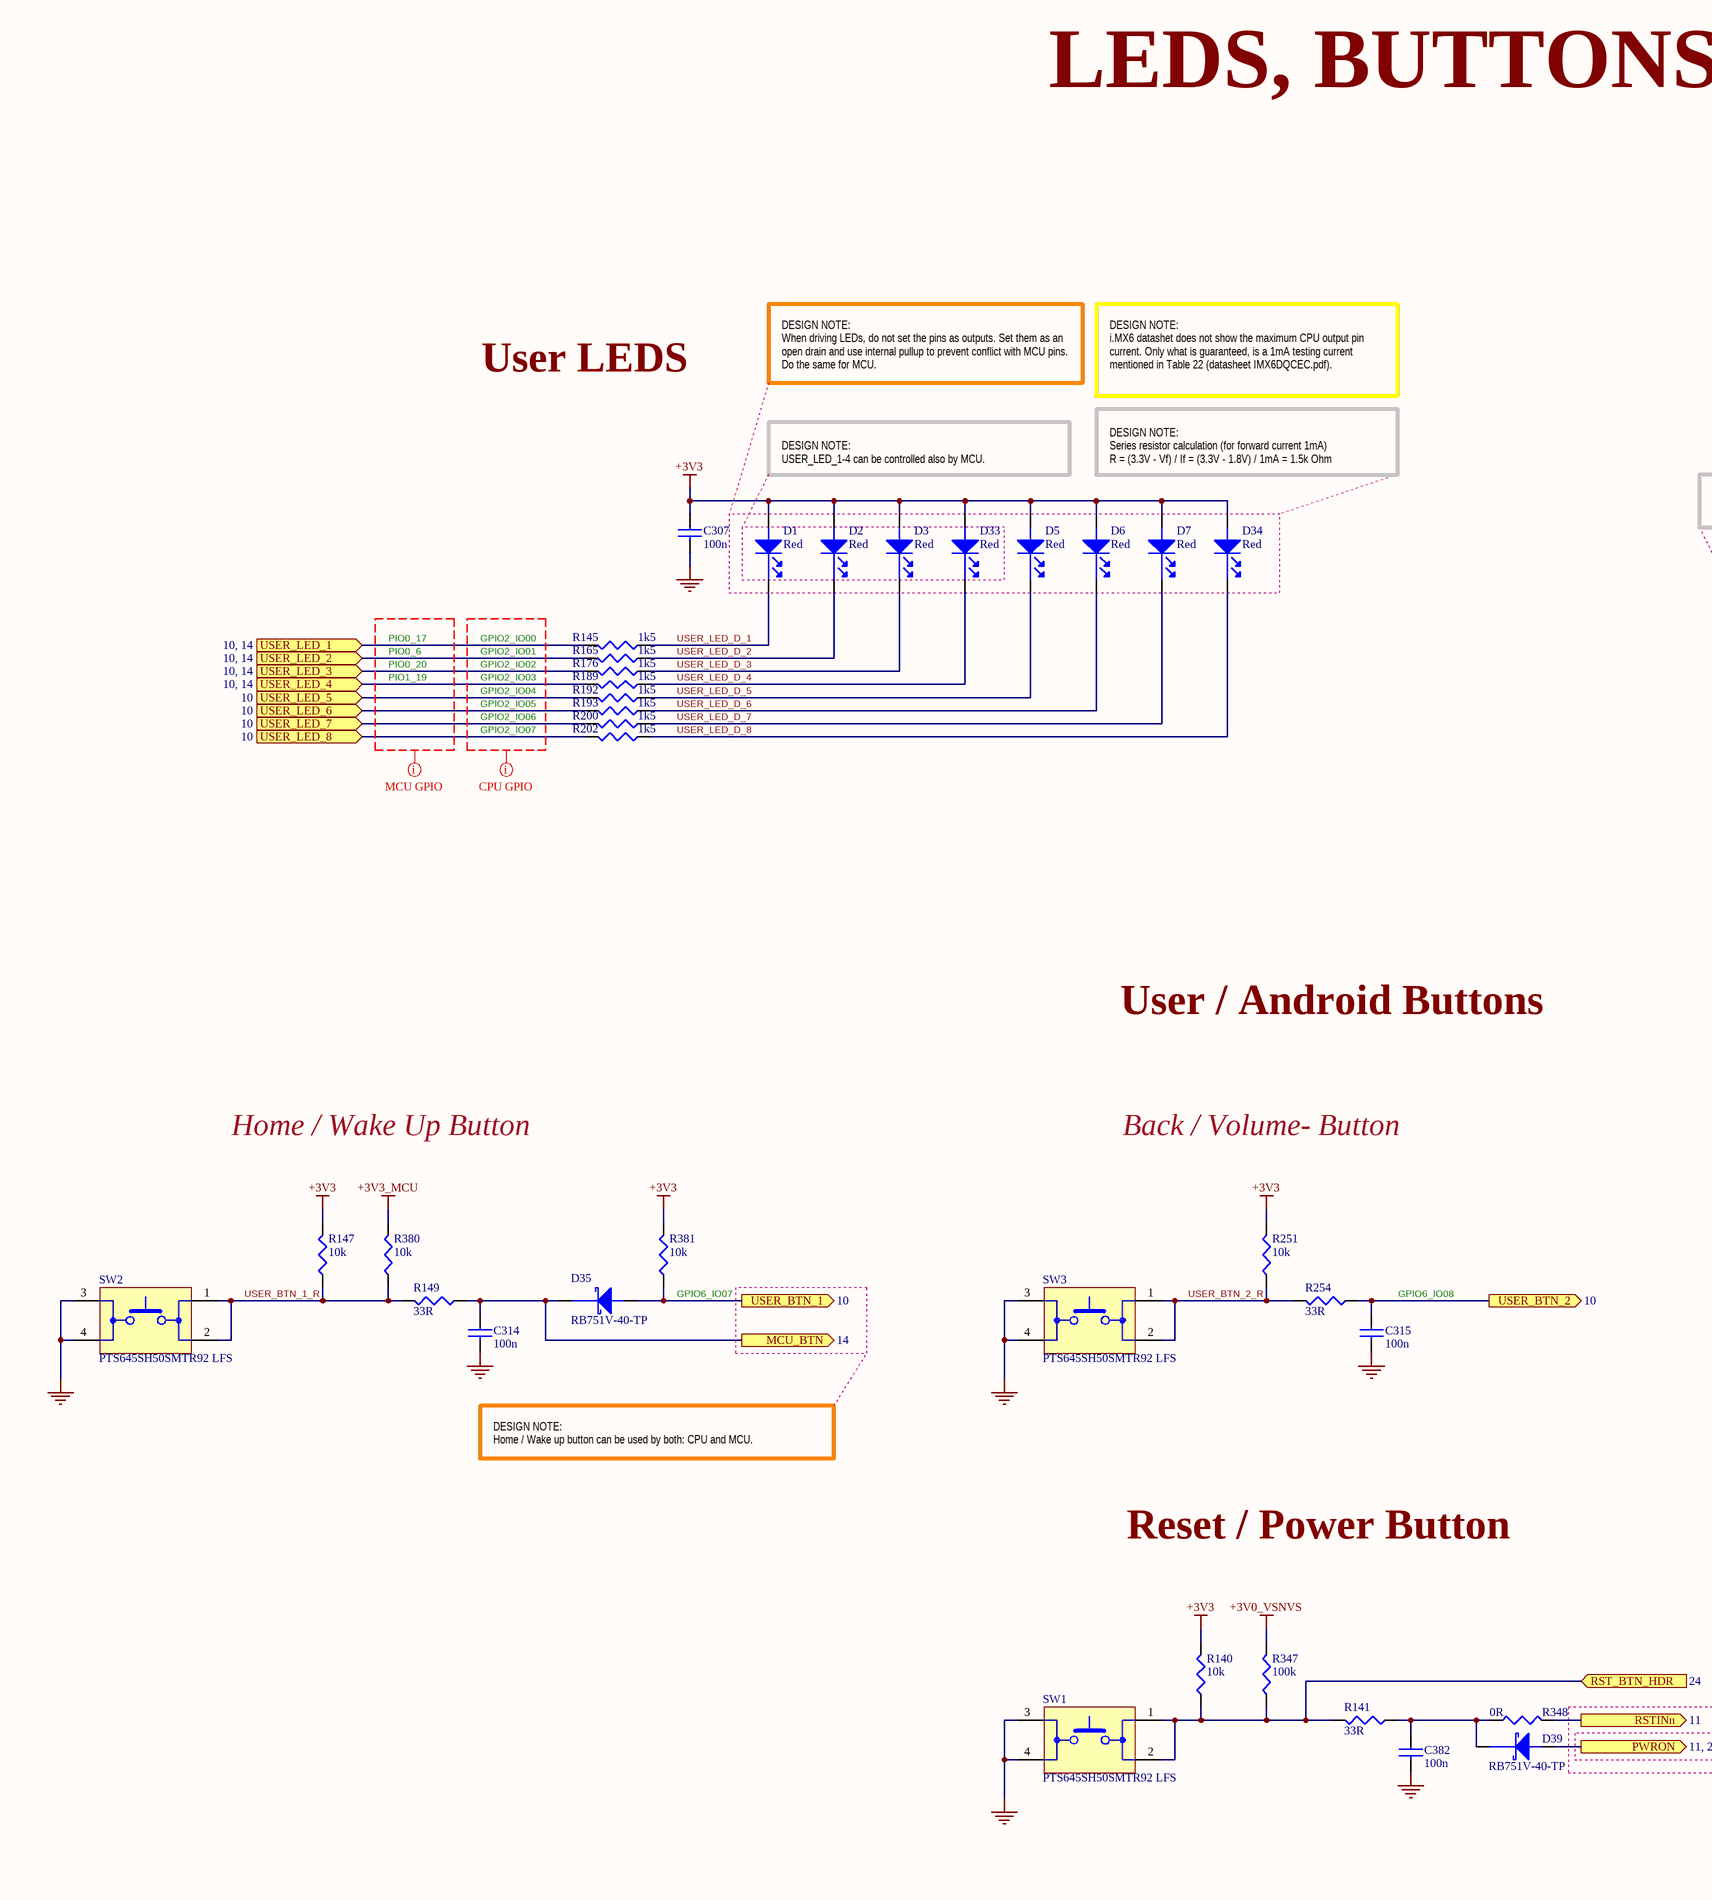
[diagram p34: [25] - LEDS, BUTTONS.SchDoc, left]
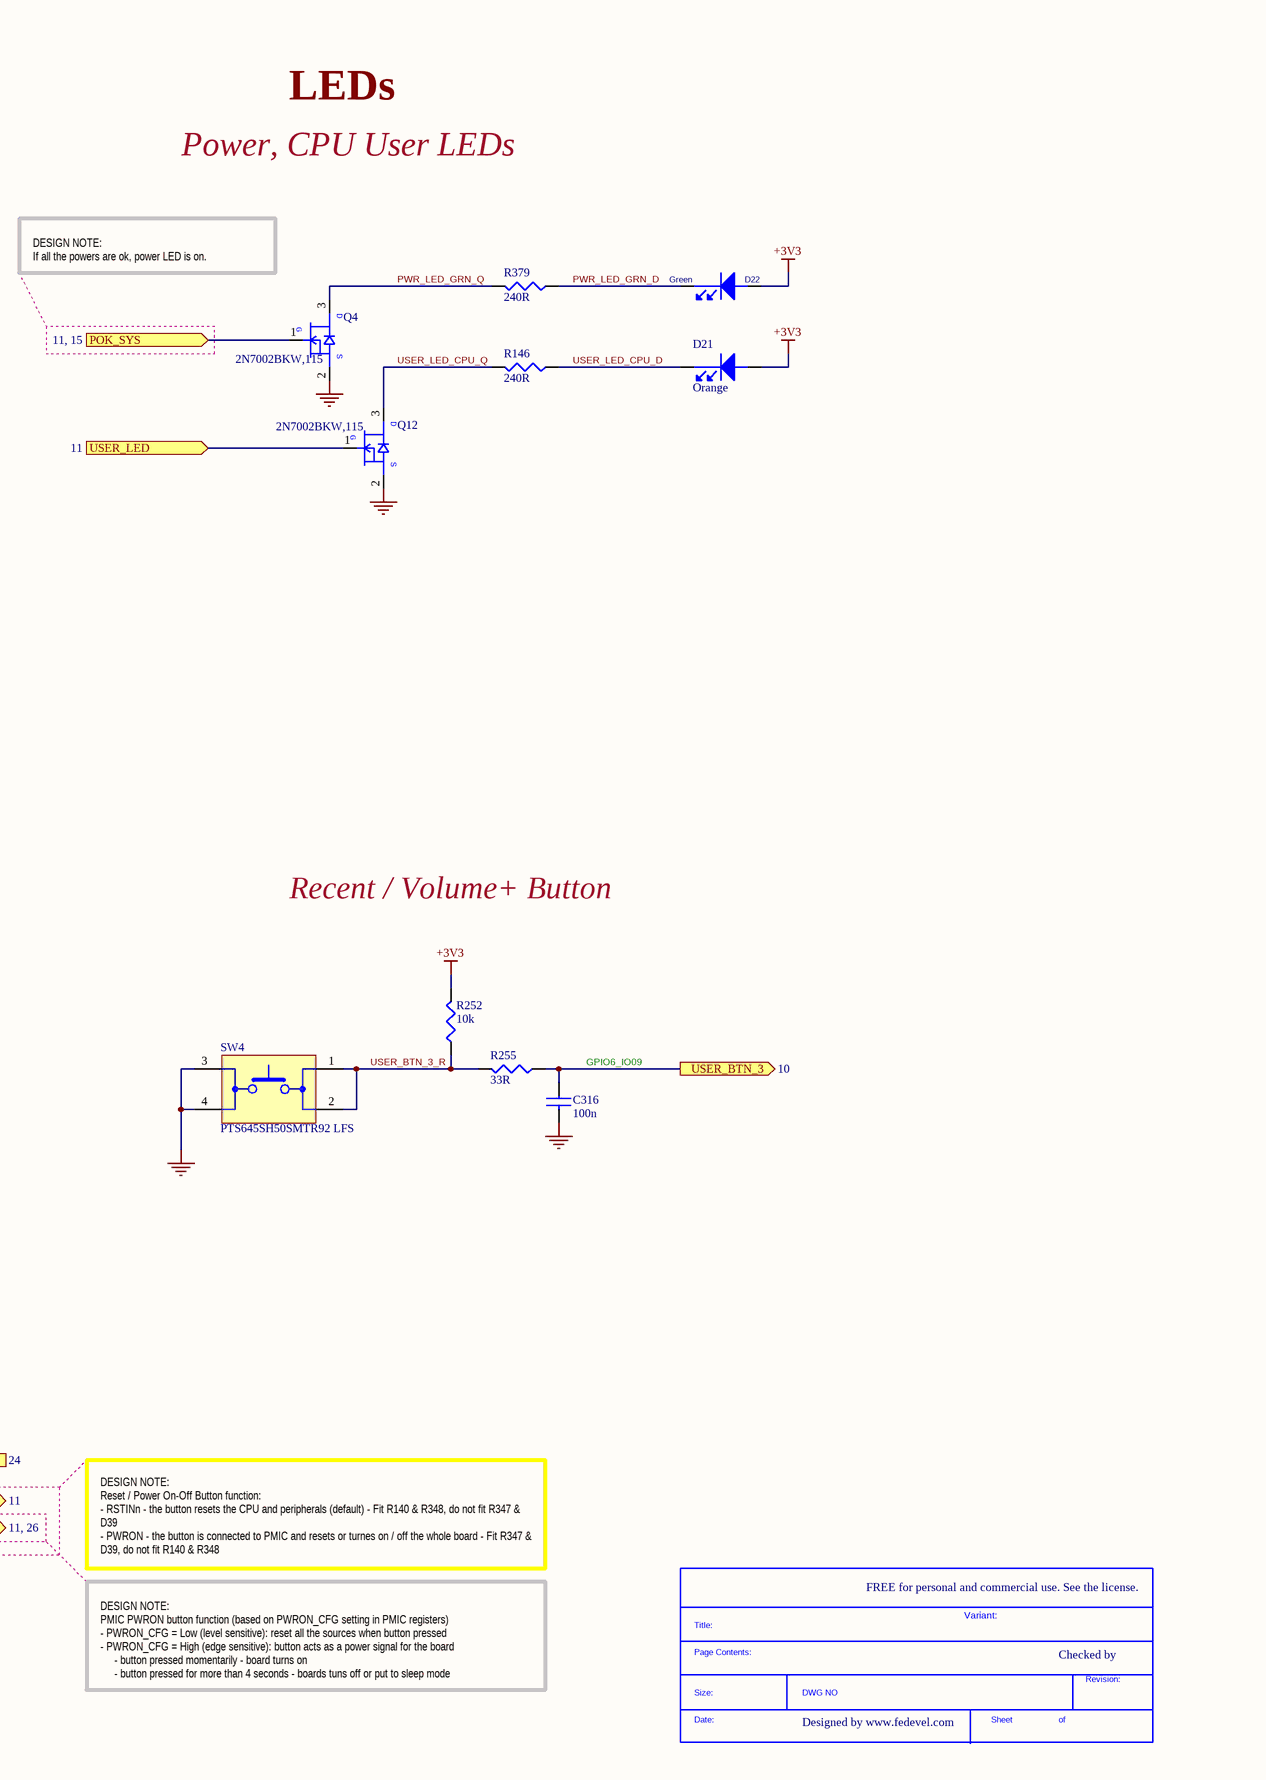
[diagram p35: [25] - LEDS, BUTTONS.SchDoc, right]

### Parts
(Parts that share a designator on the sheet are numbered #1, #2 ... from top to bottom, then left to right.)
*#21  SDTitleBlock  (value not drawn)  (graphical)
C307  100n  [C0402]
C314  100n  [C0402]
C315  100n  [C0402]
C316  100n  [C0402]
C382  100n  [C0402]
D1  Red  [LED_0603]
D2  Red  [LED_0603]
D3  Red  [LED_0603]
D5  Red  [LED_0603]
D6  Red  [LED_0603]
D7  Red  [LED_0603]
D21  Orange  [LED_0603]
D22  Green  [LED_0603]
D33  Red  [LED_0603]
D34  Red  [LED_0603]
D35  RB751V-40-TP  [SOD323]
D39  RB751V-40-TP  [SOD323]
Q4  2N7002BKW,115  [SC70_SOT323]
Q12  2N7002BKW,115  [SC70_SOT323]
R140  10k  [R0402]
R141  33R  [R0402]
R145  1k5  [R0402]
R146  240R  [R0402]
R147  10k  [R0402]
R149  33R  [R0402]
R165  1k5  [R0402]
R176  1k5  [R0402]
R189  1k5  [R0402]
R192  1k5  [R0402]
R193  1k5  [R0402]
R200  1k5  [R0402]
R202  1k5  [R0402]
R251  10k  [R0402]
R252  10k  [R0402]
R254  33R  [R0402]
R255  33R  [R0402]
R347  100k  [R0402]
R348  0R  [R0402]
R379  240R  [R0402]
R380  10k  [R0402]
R381  10k  [R0402]
SW1  PTS645SH50SMTR92 LFS  [TACT_SMD]
SW2  PTS645SH50SMTR92 LFS  [TACT_SMD]
SW3  PTS645SH50SMTR92 LFS  [TACT_SMD]
SW4  PTS645SH50SMTR92 LFS  [TACT_SMD]

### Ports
MCU_BTN (out, see 14), POK_SYS (see 11, 15), PWRON (out, see 11, 26), RST_BTN_HDR (in, see 24), RSTINn (out, see 11), USER_BTN_1 (out, see 10), USER_BTN_2 (out, see 10), USER_BTN_3 (out, see 10), USER_LED (in, see 11), USER_LED_1 (in, see 10, 14), USER_LED_2 (in, see 10, 14), USER_LED_3 (in, see 10, 14), USER_LED_4 (in, see 10, 14), USER_LED_5 (in, see 10), USER_LED_6 (in, see 10), USER_LED_7 (in, see 10), USER_LED_8 (in, see 10)

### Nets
+3V0_VSNVS: R347.2
+3V3: C307.1 D1.2(ANODE) D2.2(ANODE) D3.2(ANODE) D5.2(ANODE) D6.2(ANODE) D7.2(ANODE) D21.2(ANODE) D22.2(ANODE) D33.2(ANODE) D34.2(ANODE) R140.2 R147.2 R251.2 R252.2 R381.2
+3V3_MCU: R380.2
GND: C307.2 C314.2 C315.2 C316.2 C382.2 Q4.2(SOURCE) Q12.2(SOURCE) SW1.3(MECH1) SW1.4(MECH2) SW2.3(MECH1) SW2.4(MECH2) SW3.3(MECH1) SW3.4(MECH2) SW4.3(MECH1) SW4.4(MECH2)
MCU_BTN: C314.1 D35.1(cathode) R149.1 ; port MCU_BTN
POK_SYS: Q4.1(GATE) ; port POK_SYS
PWR_LED_GRN_D: D22.1(cathode) R379.1
PWR_LED_GRN_Q: Q4.3(DRAIN) R379.2
PWRON: D39.2(ANODE) ; port PWRON
RST_BTN_HDR: R140.1 R141.2 R347.1 SW1.1 SW1.2 ; port RST_BTN_HDR
RSTINn: R348.2 ; port RSTINn
USER_BTN_1: D35.2(ANODE) R381.1 ; port USER_BTN_1
USER_BTN_1_R: R147.1 R149.2 R380.1 SW2.1 SW2.2
USER_BTN_2: C315.1 R254.1 ; port USER_BTN_2
USER_BTN_2_R: R251.1 R254.2 SW3.1 SW3.2
USER_BTN_3: C316.1 R255.1 ; port USER_BTN_3
USER_BTN_3_R: R252.1 R255.2 SW4.1 SW4.2
USER_LED: Q12.1(GATE) ; port USER_LED
USER_LED_1: R145.2 ; port USER_LED_1
USER_LED_2: R165.2 ; port USER_LED_2
USER_LED_3: R176.2 ; port USER_LED_3
USER_LED_4: R189.2 ; port USER_LED_4
USER_LED_5: R192.2 ; port USER_LED_5
USER_LED_6: R193.2 ; port USER_LED_6
USER_LED_7: R200.2 ; port USER_LED_7
USER_LED_8: R202.2 ; port USER_LED_8
USER_LED_CPU_D: D21.1(cathode) R146.1
USER_LED_CPU_Q: Q12.3(DRAIN) R146.2
USER_LED_D_1: D1.1(cathode) R145.1
USER_LED_D_2: D2.1(cathode) R165.1
USER_LED_D_3: D3.1(cathode) R176.1
USER_LED_D_4: D33.1(cathode) R189.1
USER_LED_D_5: D5.1(cathode) R192.1
USER_LED_D_6: D6.1(cathode) R193.1
USER_LED_D_7: D7.1(cathode) R200.1
USER_LED_D_8: D34.1(cathode) R202.1
NetC382_1: C382.1 D39.1(cathode) R141.1 R348.1

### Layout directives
mark named CPU GPIO: (no net found under the mark)
mark named MCU GPIO: (no net found under the mark)

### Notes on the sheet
- LEDS, BUTTONS
- User LEDS
- DESIGN NOTE:
  When driving LEDs, do not set the pins as outputs. Set them as an open drain and use internal pullup to prevent conflict with MCU pins. Do the same for MCU.
- DESIGN NOTE:
  i.MX6 datashet does not show the maximum CPU output pin current. Only what is guaranteed, is a 1mA testing current mentioned in Table 22 (datasheet IMX6DQCEC.pdf).
- LEDs
- Power, CPU User LEDs
- DESIGN NOTE:
  USER_LED_1-4 can be controlled also by MCU.
- DESIGN NOTE:
  Series resistor calculation (for forward current 1mA)
  R = (3.3V - Vf) / If = (3.3V - 1.8V) / 1mA = 1.5k Ohm
- DESIGN NOTE:
  If all the powers are ok, power LED is on.
- PIO0_17
- GPIO2_IO00
- PIO1_19
- PIO0_6
- PIO0_20
- GPIO2_IO01
- GPIO2_IO02
- GPIO2_IO03
- GPIO2_IO04
- GPIO2_IO05
- GPIO2_IO06
- GPIO2_IO07
- User / Android Buttons
- Home / Wake Up Button
- Back / Volume- Button
- Recent / Volume+ Button
- (near R381) GPIO6_IO07
- GPIO6_IO08
- GPIO6_IO09
- DESIGN NOTE:
  Home / Wake up button can be used by both: CPU and MCU.
- Reset / Power Button
- DESIGN NOTE:
  Reset / Power On-Off Button function:
  - RSTINn - the button resets the CPU and peripherals (default) - Fit R140 & R348, do not fit R347 & D39
  - PWRON - the button is connected to PMIC and resets or turnes on / off the whole board - Fit R347 & D39, do not fit R140 & R348
- FREE for personal and commercial use. See the license.
- Variant:
- Checked by
- DESIGN NOTE:
  PMIC PWRON button function (based on PWRON_CFG setting in PMIC registers)
  - PWRON_CFG = Low (level sensitive): reset all the sources when button pressed
  - PWRON_CFG = High (edge sensitive): button acts as a power signal for the board
  - button pressed momentarily - board turns on
  - button pressed for more than 4 seconds - boards tuns off or put to sleep mode
- Designed by www.fedevel.com

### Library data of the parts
C307 C314-C316 C382 = C1005X5R1H104K: as C219 on sheet [14] - MCU
D1-D3 D5-D7 D33 D34 = LS L29K-H1J2-1-Z: LED SMARTLED RED 630NM 0603 SMD; Manufacturer: OSRAM Opto Semiconductors Inc; Millicandela Rating: 4.95mcd; Voltage - Forward (Vf) Typ: 1.8V; Current - Test: 2mA; Wavelength - Peak: 643nm; Viewing Angle: 160°; Lens Type: Diffused; Lens Style/Size: Rectangle with Flat Top, 1.3mm x 0.8mm; Luminous Flux @ Current - Test: 20 mlm; .Checked PCB: used
D21 = LO L29K-H2K1-24-Z: as D24 on sheet [14] - MCU
D22 = LG L29K-G2J1-24-Z: LED SMARTLED GREEN 570NM 0603; Manufacturer: OSRAM Opto Semiconductors Inc; .Checked PCB: used; Current - Test: 2mA; Voltage - Forward (Vf) Typ: 1.7V; Luminous Flux @ Current - Test: 12 mlm; Millicandela Rating: 3.92mcd; Wavelength - Peak: 572nm; Lens Type: Diffused; Lens Style/Size: Rectangle with Flat Top, 1.3mm x 0.8mm; Viewing Angle: 160°; Regulator Topology: Positive Fixed; Voltage - Output: 2.5V; Voltage - Input: 2.6 V ~ 6 V; Voltage - Dropout (Typical): 0.16V @ 500mA; Number of Regulators: 1; Current - Output: 500mA; Current - Limit (Min): 600mA
D35 D39 = RB751V-40-TP: as D36 on sheet [14] - MCU
Q4 Q12 = 2N7002BKW,115: as Q5 on sheet [14] - MCU
R140 R147 R251 R252 R380 R381 = RC0402FR-0710KL: as R270 on sheet [14] - MCU
R141 R149 R254 R255 = RMCF0402FT33R0: as R299 on sheet [14] - MCU
R145 R165 R176 R189 R192 R193 R200 R202 = RC0402FR-071K5L: as R387 on sheet [14] - MCU
R146 R379 = RMCF0402FT240R: as R186 on sheet [14] - MCU
R347 = RMCF0402FT100K: as R393-R396 on sheet [14] - MCU
R348 = RC0402JR-070RL: as R204 on sheet [14] - MCU
SW1-SW4 = PTS645SH50SMTR92 LFS: SWITCH TACTILE SPST-NO 0.05A 12V; Manufacturer: C&K Components; Switch Function: Off-Mom; Contact Rating @ Voltage: 0.05A @ 12VDC; Actuator Type: Standard; Actuator Height off PCB, from Pins: 5.00mm; Actuator Orientation: Top Actuated; Outline: 6.00mm x 6.00mm; Illumination: Non-Illuminated; Operating Force: 200gf; Actuator Material: Polyamide (PA66), Nylon 6/6; Mechanical Life: 100,000 Cycles; .Checked PCB: MM

## Sheet [26] - PWR PMIC.SchDoc
size A2; DocumentNumber: 26; SheetNumber: 26; SheetTotal: 31
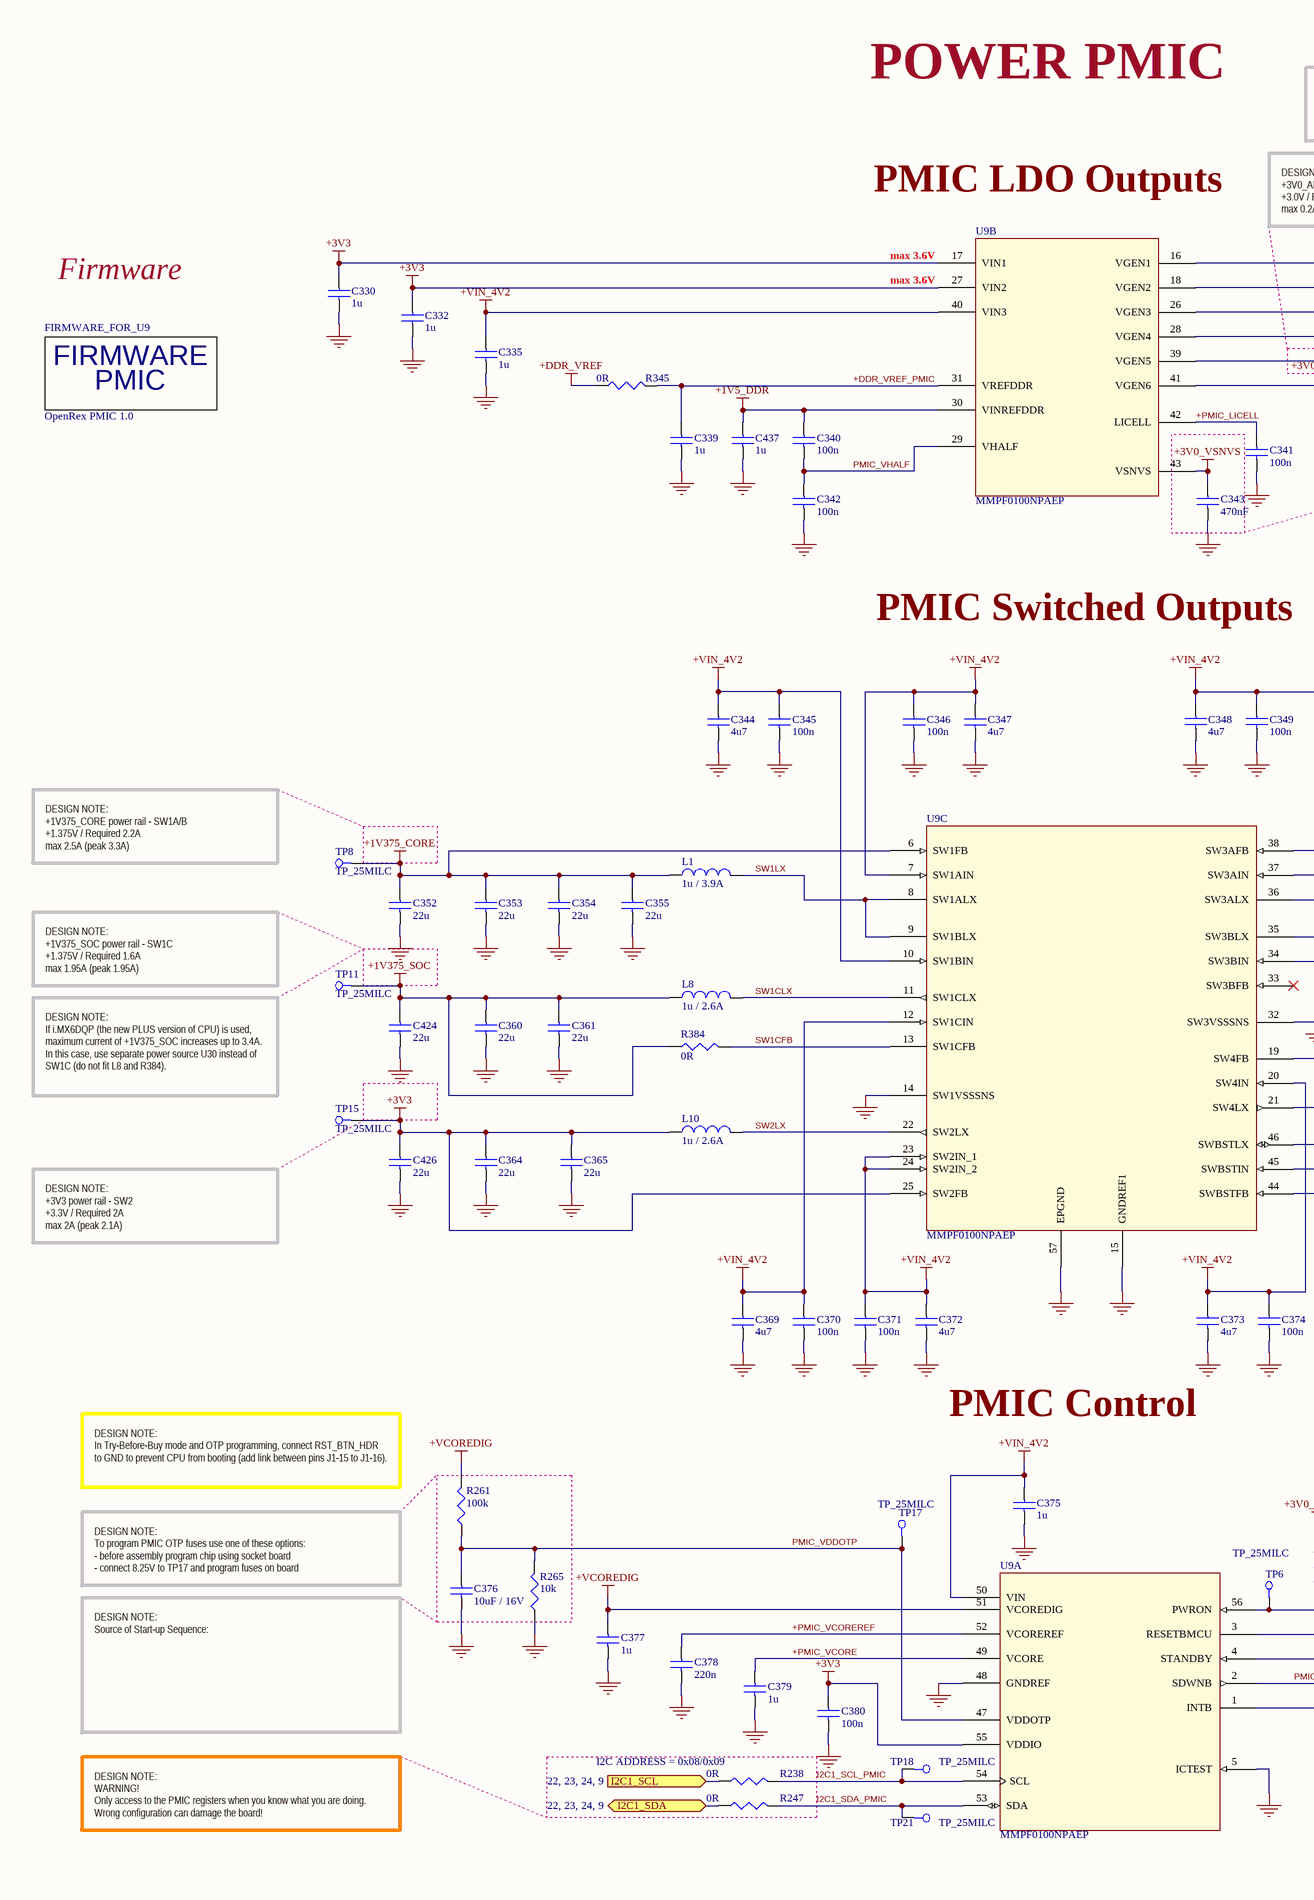
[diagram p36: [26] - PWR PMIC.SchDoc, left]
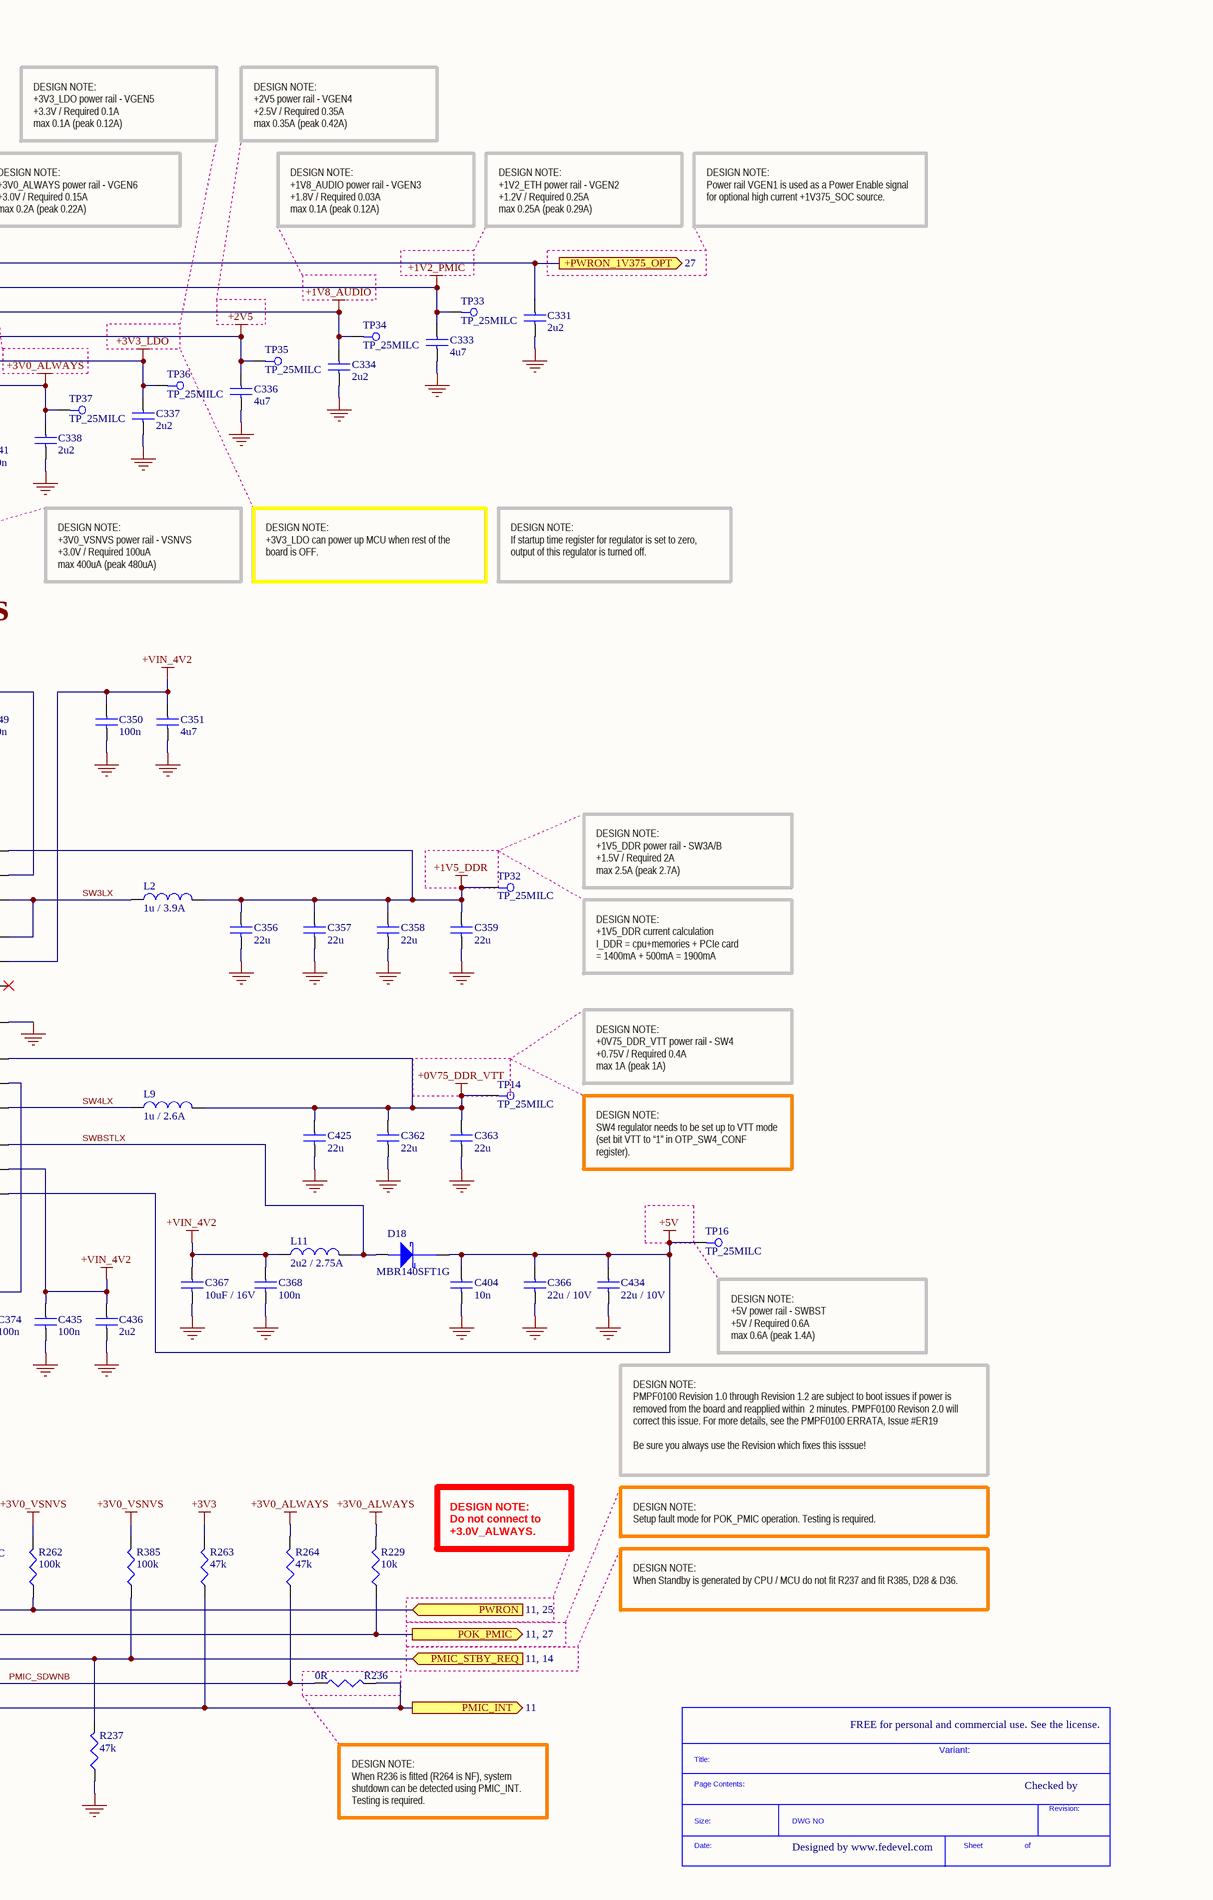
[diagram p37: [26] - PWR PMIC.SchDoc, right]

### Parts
(Parts that share a designator on the sheet are numbered #1, #2 ... from top to bottom, then left to right.)
*#22  SDTitleBlock  (value not drawn)  (graphical)
C330  1u  [C0402]
C331  2u2  [C0402]
C332  1u  [C0402]
C333  4u7  [C0402]
C334  2u2  [C0402]
C335  1u  [C0402]
C336  4u7  [C0402]
C337  2u2  [C0402]
C338  2u2  [C0402]
C339  1u  [C0402]
C340  100n  [C0402]
C341  100n  [C0402]
C342  100n  [C0402]
C343  470nF  [C0402]
C344  4u7  [C0402]
C345  100n  [C0402]
C346  100n  [C0402]
C347  4u7  [C0402]
C348  4u7  [C0402]
C349  100n  [C0402]
C350  100n  [C0402]
C351  4u7  [C0402]
C352  22u  [C0603]
C353  22u  [C0603]
C354  22u  [C0603]
C355  22u  [C0603]
C356  22u  [C0603]
C357  22u  [C0603]
C358  22u  [C0603]
C359  22u  [C0603]
C360  22u  [C0603]
C361  22u  [C0603]
C362  22u  [C0603]
C363  22u  [C0603]
C364  22u  [C0603]
C365  22u  [C0603]
C366  22u / 10V  [C0603]
C367  10uF / 16V  [C0805]
C368  100n  [C0402]
C369  4u7  [C0402]
C370  100n  [C0402]
C371  100n  [C0402]
C372  4u7  [C0402]
C373  4u7  [C0402]
C374  100n  [C0402]
C375  1u  [C0402]
C376  10uF / 16V  [C0805]
C377  1u  [C0402]
C378  220n  [C0402]
C379  1u  [C0402]
C380  100n  [C0402]
C404  10n  [C0402]
C424  22u  [C0603]
C425  22u  [C0603]
C426  22u  [C0603]
C434  22u / 10V  [C0603]
C435  100n  [C0402]
C436  2u2  [C0402]
C437  1u  [C0402]
D18  MBR140SFT1G  [SOD-123FL]
FIRMWARE_FOR_U9  OpenRex PMIC 1.0  (mechanical)
L1  1u / 3.9A  [IHLP_118MILX144MIL]
L2  1u / 3.9A  [IHLP_118MILX144MIL]
L8  1u / 2.6A  [IFSC_79MILX98MIL]
L9  1u / 2.6A  [IFSC_79MILX98MIL]
L10  1u / 2.6A  [IFSC_79MILX98MIL]
L11  2u2 / 2.75A  [IHLP_160MILX175MIL]
R229  10k  [R0402]
R236  0R  [R0402]
R237  47k  [R0402]
R238  0R  [R0402]
R247  0R  [R0402]
R261  100k  [R0402]
R262  100k  [R0402]
R263  47k  [R0402]
R264  47k  [R0402]
R265  10k  [R0402]
R345  0R  [R0402]
R384  0R  [R0402]
R385  100k  [R0402]
TP6  TP_25MILC  [TP_25C]  (no BOM)
TP8  TP_25MILC  [TP_25C]  (no BOM)
TP11  TP_25MILC  [TP_25C]  (no BOM)
TP14  TP_25MILC  [TP_25C]  (no BOM)
TP15  TP_25MILC  [TP_25C]  (no BOM)
TP16  TP_25MILC  [TP_25C]  (no BOM)
TP17  TP_25MILC  [TP_25C]  (no BOM)
TP18  TP_25MILC  [TP_25C]  (no BOM)
TP21  TP_25MILC  [TP_25C]  (no BOM)
TP32  TP_25MILC  [TP_25C]  (no BOM)
TP33  TP_25MILC  [TP_25C]  (no BOM)
TP34  TP_25MILC  [TP_25C]  (no BOM)
TP35  TP_25MILC  [TP_25C]  (no BOM)
TP36  TP_25MILC  [TP_25C]  (no BOM)
TP37  TP_25MILC  [TP_25C]  (no BOM)
U9  MMPF0100NPAEP  [56-VFQFN EP]  (parts A,B,C of 3)

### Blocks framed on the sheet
I2C ADDRESS = 0x08/0x09: R238 R247

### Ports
+PWRON_1V375_OPT (see 27), I2C1_SCL (see 22, 23, 24, 9), I2C1_SDA (bidir, see 22, 23, 24, 9), PMIC_INT (out, see 11), PMIC_STBY_REQ (in, see 11, 14), POK_PMIC (see 11, 27), PWRON (in, see 11, 25)

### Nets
+0V75_DDR_VTT: C362.1 C363.1 C425.1 L9.2 TP14.1 U9.19(SW4FB)
+1V2_PMIC: C333.1 TP33.1 U9.18(VGEN2)
+1V5_DDR: C340.1 C356.1 C357.1 C358.1 C359.1 C437.1 L2.2 TP32.1 U9.30(VINREFDDR) U9.38(SW3AFB)
+1V8_AUDIO: C334.1 TP34.1 U9.26(VGEN3)
+1V375_CORE: C352.1 C353.1 C354.1 C355.1 L1.2 TP8.1 U9.6(SW1FB)
+1V375_SOC: C360.1 C361.1 C424.1 L8.1 R384.1 TP11.1
+2V5: C336.1 TP35.1 U9.28(VGEN4)
+3V0_ALWAYS: C338.1 R229.2 R264.2 TP37.1 U9.41(VGEN6)
+3V0_VSNVS: C343.1 R262.2 R385.2 U9.43(VSNVS)
+3V3: C330.1 C332.1 C364.1 C365.1 C380.1 C426.1 L10.2 R263.2 TP15.1 U9.17(VIN1) U9.25(SW2FB) U9.27(VIN2) U9.55(VDDIO)
+3V3_LDO: C337.1 TP36.1 U9.39(VGEN5)
+5V: C366.1 C404.1 C434.1 D18.1(Cathode) TP16.1 U9.44(SWBSTFB)
+DDR_VREF: R345.1
+VCOREDIG: C377.1 R261.2 U9.51(VCOREDIG)
+VIN_4V2: C335.1 C344.1 C345.1 C346.1 C347.1 C348.1 C349.1 C350.1 C351.1 C367.1 C368.1 C369.1 C370.1 C371.1 C372.1 C373.1 C374.1 C375.1 C435.1 C436.1 L11.1 U9.7(SW1AIN) U9.10(SW1BIN) U9.12(SW1CIN) U9.20(SW4IN) U9.23(SW2IN_1) U9.24(SW2IN_2) U9.34(SW3BIN) U9.37(SW3AIN) U9.40(VIN3) U9.45(SWBSTIN) U9.50(VIN)
GND: C330.2 C331.2 C332.2 C333.2 C334.2 C335.2 C336.2 C337.2 C338.2 C339.2 C341.2 C342.2 C343.2 C344.2 C345.2 C346.2 C347.2 C348.2 C349.2 C350.2 C351.2 C352.2 C353.2 C354.2 C355.2 C356.2 C357.2 C358.2 C359.2 C360.2 C361.2 C362.2 C363.2 C364.2 C365.2 C366.2 C367.2 C368.2 C369.2 C370.2 C371.2 C372.2 C373.2 C374.2 C375.2 C376.2 C377.2 C378.2 C379.2 C380.2 C404.2 C424.2 C425.2 C426.2 C434.2 C435.2 C436.2 C437.2 R237.1 R265.1 U9.5(ICTEST) U9.14(SW1VSSSNS) U9.15(GNDREF1) U9.32(SW3VSSSNS) U9.48(GNDREF) U9.57(EPGND)
+DDR_VREF_PMIC: C339.1 R345.2 U9.31(VREFDDR)
+PMIC_LICELL: C341.1 U9.42(LICELL)
+PMIC_VCORE: C379.1 U9.49(VCORE)
+PMIC_VCOREREF: C378.1 U9.52(VCOREREF)
+PWRON_1V375_OPT: C331.1 U9.16(VGEN1) ; port +PWRON_1V375_OPT
I2C1_SCL: R238.1 ; port I2C1_SCL
I2C1_SCL_PMIC: R238.2 TP18.1 U9.54(SCL)
I2C1_SDA: R247.1 ; port I2C1_SDA
I2C1_SDA_PMIC: R247.2 TP21.1 U9.53(SDA)
PMIC_INT: R236.2 R263.1 U9.1(INTB) ; port PMIC_INT
PMIC_SDWNB: R236.1 R264.1 U9.2(SDWNB)
PMIC_STBY_REQ: R237.2 R385.1 U9.4(STANDBY) ; port PMIC_STBY_REQ
PMIC_VDDOTP: C376.1 R261.1 R265.2 TP17.1 U9.47(VDDOTP)
PMIC_VHALF: C340.2 C342.1 U9.29(VHALF)
POK_PMIC: R229.1 U9.3(RESETBMCU) ; port POK_PMIC
PWRON: R262.1 TP6.1 U9.56(PWRON) ; port PWRON
SW1CFB: R384.2 U9.13(SW1CFB)
SW1CLX: L8.2 U9.11(SW1CLX)
SW1LX: L1.1 U9.8(SW1ALX) U9.9(SW1BLX)
SW2LX: L10.1 U9.22(SW2LX)
SW3LX: L2.1 U9.35(SW3BLX) U9.36(SW3ALX)
SW4LX: L9.1 U9.21(SW4LX)
SWBSTLX: D18.2(Anode) L11.2 U9.46(SWBSTLX)

Not connected (* = marked no-connect by the designer): U9 33(SW3BFB)*

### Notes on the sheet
- POWER PMIC
- DESIGN NOTE:
  +3V3_LDO power rail - VGEN5
  +3.3V / Required 0.1A
  max 0.1A (peak 0.12A)
- DESIGN NOTE:
  +2V5 power rail - VGEN4
  +2.5V / Required 0.35A
  max 0.35A (peak 0.42A)
- PMIC LDO Outputs
- DESIGN NOTE:
  +3V0_ALWAYS power rail - VGEN6
  +3.0V / Required 0.15A
  max 0.2A (peak 0.22A)
- DESIGN NOTE:
  +1V8_AUDIO power rail - VGEN3
  +1.8V / Required 0.03A
  max 0.1A (peak 0.12A)
- DESIGN NOTE:
  +1V2_ETH power rail - VGEN2
  +1.2V / Required 0.25A
  max 0.25A (peak 0.29A)
- (near U9) max 3.6V
- DESIGN NOTE:
  Power rail VGEN1 is used as a Power Enable signal for optional high current +1V375_SOC source.
- Firmware
- DESIGN NOTE:
  +3V0_VSNVS power rail - VSNVS
  +3.0V / Required 100uA
  max 400uA (peak 480uA)
- DESIGN NOTE:
  +3V3_LDO can power up MCU when rest of the board is OFF.
- DESIGN NOTE:
  If startup time register for regulator is set to zero, output of this regulator is turned off.
- PMIC Switched Outputs
- DESIGN NOTE:
  +1V375_CORE power rail - SW1A/B
  +1.375V / Required 2.2A
  max 2.5A (peak 3.3A)
- DESIGN NOTE:
  +1V5_DDR power rail - SW3A/B
  +1.5V / Required 2A
  max 2.5A (peak 2.7A)
- DESIGN NOTE:
  +1V375_SOC power rail - SW1C
  +1.375V / Required 1.6A
  max 1.95A (peak 1.95A)
- DESIGN NOTE:
  +1V5_DDR current calculation
  I_DDR = cpu+memories + PCIe card
  = 1400mA + 500mA = 1900mA
- DESIGN NOTE:
  +0V75_DDR_VTT power rail - SW4
  +0.75V / Required 0.4A
  max 1A (peak 1A)
- DESIGN NOTE:
  If i.MX6DQP (the new PLUS version of CPU) is used, maximum current of +1V375_SOC increases up to 3.4A.
  In this case, use separate power source U30 instead of SW1C (do not fit L8 and R384).
- DESIGN NOTE:
  SW4 regulator needs to be set up to VTT mode (set bit VTT to “1” in OTP_SW4_CONF register).
- DESIGN NOTE:
  +3V3 power rail - SW2
  +3.3V / Required 2A
  max 2A (peak 2.1A)
- DESIGN NOTE:
  +5V power rail - SWBST
  +5V / Required 0.6A
  max 0.6A (peak 1.4A)
- PMIC Control
- DESIGN NOTE:
  In Try-Before-Buy mode and OTP programming, connect RST_BTN_HDR to GND to prevent CPU from booting (add link between pins J1-15 to J1-16).
- DESIGN NOTE:
  PMPF0100 Revision 1.0 through Revision 1.2 are subject to boot issues if power is removed from the board and reapplied within  2 minutes. PMPF0100 Revison 2.0 will correct this issue. For more details, see the PMPF0100 ERRATA, Issue #ER19
  Be sure you always use the Revision which fixes this isssue!
- DESIGN NOTE:
  Do not connect to +3.0V_ALWAYS.
- DESIGN NOTE:
  Setup fault mode for POK_PMIC operation. Testing is required.
- DESIGN NOTE:
  To program PMIC OTP fuses use one of these options:
  - before assembly program chip using socket board
  - connect 8.25V to TP17 and program fuses on board
- DESIGN NOTE:
  When Standby is generated by CPU / MCU do not fit R237 and fit R385, D28 & D36.
- DESIGN NOTE:
  Source of Start-up Sequence:
- FREE for personal and commercial use. See the license.
- Variant:
- Checked by
- DESIGN NOTE:
  WARNING!
  Only access to the PMIC registers when you know what you are doing. Wrong configuration can damage the board!
- DESIGN NOTE:
  When R236 is fitted (R264 is NF), system shutdown can be detected using PMIC_INT. Testing is required.
- Designed by www.fedevel.com

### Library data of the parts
C330 C332 C335 C339 C375 C377 C379 C437 = C1005X5R1C105K: CAP CER 1.0UF 16V X5R 0402; Manufacturer: TDK Corporation; Capacitance: 1.0µF; Value: 1uF; .Checked PCB: used; Tolerance: ±10%
C331 C334 C337 C338 C436 = C1005X5R1A225K: CAP CER 2.2UF 10V 10% X5R 0402; Manufacturer: TDK Corporation; Capacitance: 2.2µF; .Checked PCB: used
C333 C336 C344 C347 C348 C351 C369 C372 C373 = C1005X5R1A475M: CAP CER 4.7UF 10V 20% X5R 0402; Manufacturer: TDK Corporation; Capacitance: 4.7µF; .Checked PCB: used
C340-C342 C345 C346 C349 C350 C368 C370 C371 C374 C380 C435 = C1005X5R1H104K: as C219 on sheet [14] - MCU
C343 = C1005X5R1C474K: CAP CER .47UF 16V X5R 0402; Manufacturer: TDK Corporation; Capacitance: 0.47µF; .Checked PCB: used; Tolerance: ±10%
C352-C363 C424 C425 = GRM188R60G226MEA0L: CAP CER 22UF 4V 20% X5R 0603; Manufacturer: Murata Electronics North America; Capacitance: 22µF; .Checked PCB: used; .Creator: MM
C364 C365 C426 = C1608X5R0J226M080AC: CAP CER 22UF 6.3V 20% X5R 0603; Manufacturer: TDK Corporation; Capacitance: 22µF; .Creator: MM
C366 C434 = C1608X5R1A226M080AC: CAP CER 22UF 10V X5R 0603; Manufacturer: TDK Corporation; Capacitance: 22µF; Tolerance: ±20%; .Creator: MM
C367 C376 = C2012X5R1C106M: CAP CER 10UF 16V 20% X5R 0805; Manufacturer: TDK Corporation; Manufacturer Part Number: C2012X5R1C106M/1.25; Capacitance: 10µF; .Checked PCB: used
C378 = C1005X5R1E224M: CAP CER .22UF 25V X5R 20% 0402; Manufacturer: TDK Corporation; Capacitance: 0.22µF; Value: 220nF; .Checked PCB: used
C404 = C1005X7R1H103K: as C220 on sheet [14] - MCU
D18 = MBR140SFT1G: DIODE SCHOTTKY 40V 1A SOD123L; Manufacturer: ON Semiconductor; Voltage - Forward (Vf) (Max) @ If: 550mV @ 1A; Speed: Fast Recovery =< 500ns, > 200mA (Io); Current - Reverse Leakage @ Vr: 500µA @ 40V; .Creator: MM
FIRMWARE_FOR_U9 = FIRMWARE_OpenRex_PMIC_1.0: .Creator: MM
L1 L2 = IHLP1212AEER1R0M11: FIXED IND 1UH 3.9A 33 MOHM SMD; Manufacturer: Vishay Dale; Type: Molded; Inductance: 1µH; Tolerance: ±20%; Current - Saturation: 5.3A; Shielding: Shielded; DC Resistance (DCR): 33 mOhm Max; Frequency - Test: 100kHz; .Creator: MM
L8-L10 = IFSC1008ABER1R0M01: FIXED IND 1UH 2.6A 43 MOHM SMD; Manufacturer: Vishay Dale; Inductance: 1µH; Tolerance: ±20%; Current - Saturation: 2.7A; Shielding: Shielded; DC Resistance (DCR): 43 mOhm Max; Frequency - Test: 100kHz; .Creator: MM
L11 = IHLP1616ABER2R2M11: FIXED IND 2.2UH 2.75A 83.5 MOHM; Manufacturer: Vishay Dale; Type: Molded; Inductance: 2.2µH; Tolerance: ±20%; Current - Saturation: 3A; Shielding: Shielded; DC Resistance (DCR): 83.5 mOhm Max; Frequency - Self Resonant: 49MHz; Frequency - Test: 100kHz; .Creator: MM
R229 R265 = RC0402FR-0710KL: as R270 on sheet [14] - MCU
R236 R238 R247 R345 R384 = RC0402JR-070RL: as R204 on sheet [14] - MCU
R237 R263 R264 = RC0402FR-0747KL: RES 47.0K OHM 1/16W 1% 0402 SMD; Manufacturer: Yageo; Power (Watts): 0.063W, 1/16W; .Checked PCB: used; Temperature Coefficient: ±100ppm/°C
R261 R262 R385 = RMCF0402FT100K: as R393-R396 on sheet [14] - MCU
TP6 TP8 TP11 TP14-TP18 TP21 TP32-TP37 = TP_25MILC: Test Point 25mil
U9 = MMPF0100NPAEP: IC PWR MGMT I.MX6 56QFN; Manufacturer: Freescale Semiconductor; Voltage - Input: 2.8 V ~ 4.5 V; Number of Outputs: 12; Voltage - Output: Multiple; .Creator: MM

## Sheet [27] - PWR 1V375 OPT, 3V3 OPT.SchDoc
size A2; DocumentNumber: 27; SheetNumber: 27; SheetTotal: 31
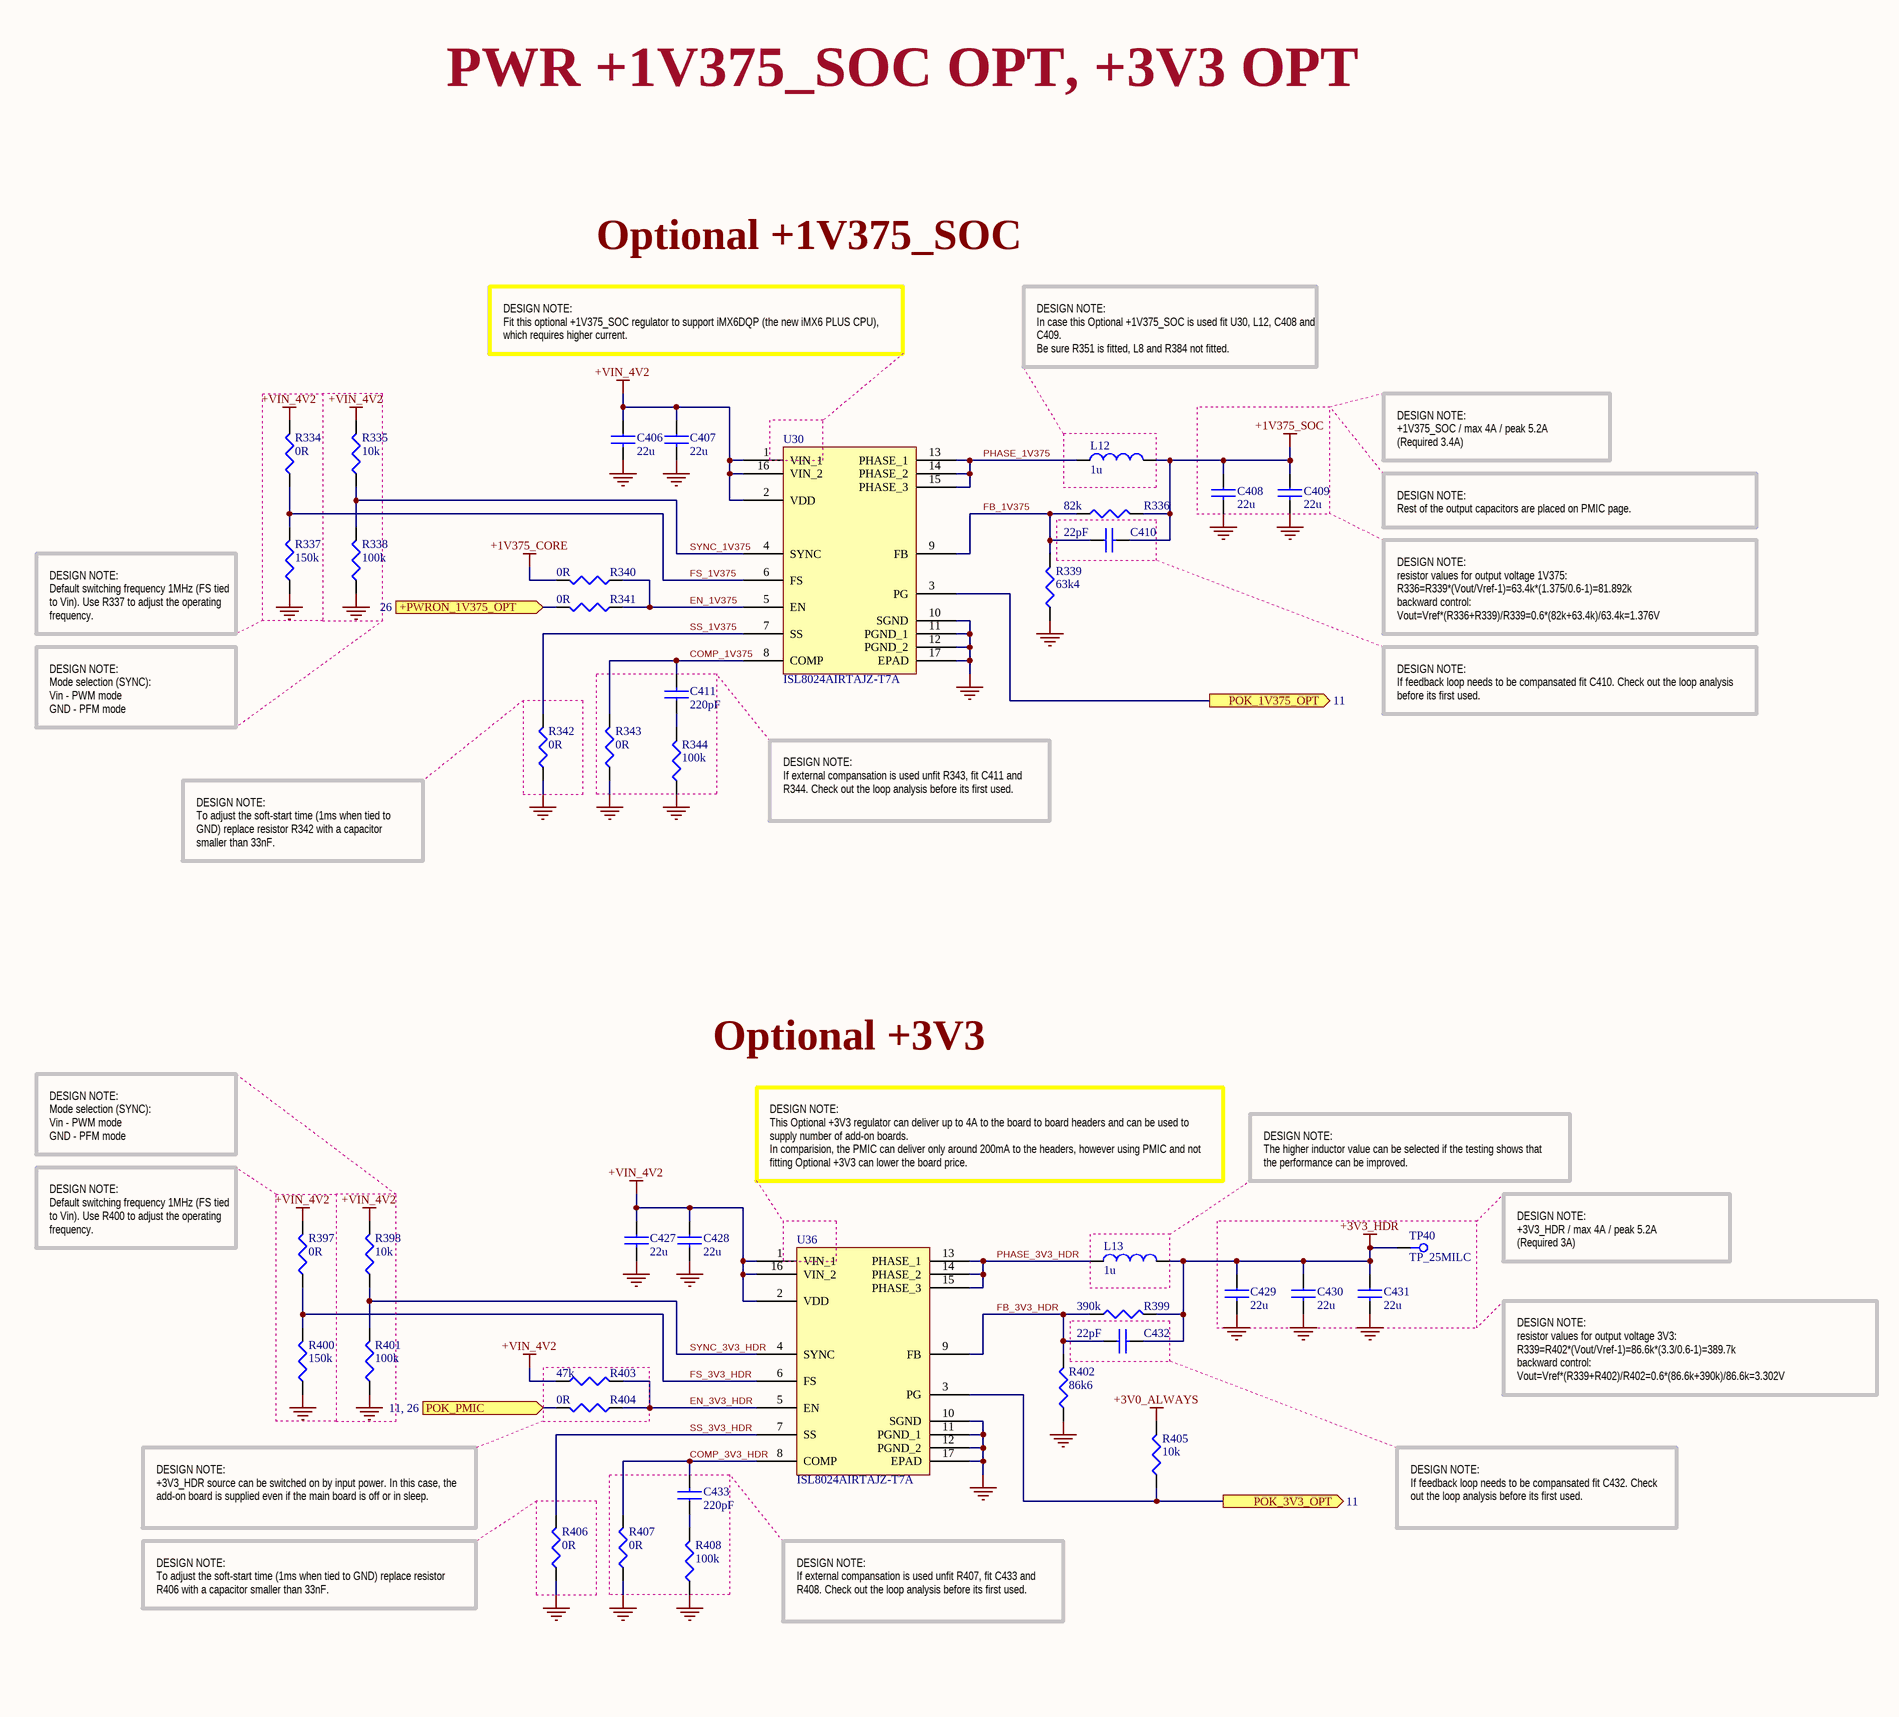
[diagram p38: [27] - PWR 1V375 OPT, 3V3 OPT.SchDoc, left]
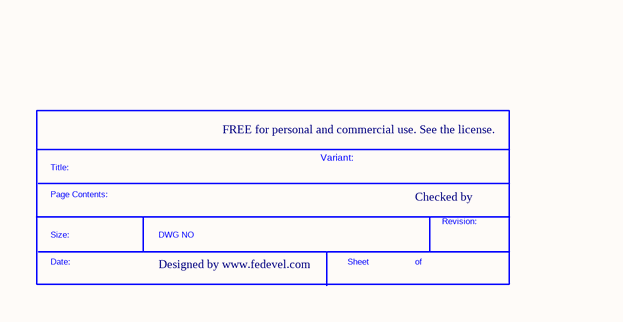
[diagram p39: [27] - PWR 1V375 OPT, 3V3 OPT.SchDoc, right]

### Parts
(Parts that share a designator on the sheet are numbered #1, #2 ... from top to bottom, then left to right.)
*#23  SDTitleBlock  (value not drawn)  (graphical)
C406  22u  [C0603]
C407  22u  [C0603]
C408  22u  [C0603]
C409  22u  [C0603]
C410  22pF  [C0402]
C411  220pF  [C0402]
C427  22u  [C0603]
C428  22u  [C0603]
C429  22u  [C0603]
C430  22u  [C0603]
C431  22u  [C0603]
C432  22pF  [C0402]
C433  220pF  [C0402]
L12  1u  [IHLP_204MILX216MIL]
L13  1u  [IHLP_204MILX216MIL]
R334  0R  [R0402]
R335  10k  [R0402]
R336  82k  [R0402]
R337  150k  [R0402]
R338  100k  [R0402]
R339  63k4  [R0402]
R340  0R  [R0402]
R341  0R  [R0402]
R342  0R  [R0402]
R343  0R  [R0402]
R344  100k  [R0402]
R397  0R  [R0402]
R398  10k  [R0402]
R399  390k  [R0402]
R400  150k  [R0402]
R401  100k  [R0402]
R402  86k6  [R0402]
R403  47k  [R0402]
R404  0R  [R0402]
R405  10k  [R0402]
R406  0R  [R0402]
R407  0R  [R0402]
R408  100k  [R0402]
TP40  TP_25MILC  [TP_25C]  (no BOM)
U30  ISL8024AIRTAJZ-T7A  [16-TQFN_3mmx3mm_V1.1]
U36  ISL8024AIRTAJZ-T7A  [16-TQFN_3mmx3mm_V1.1]

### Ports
+PWRON_1V375_OPT (see 26), POK_1V375_OPT (out, see 11), POK_3V3_OPT (out, see 11), POK_PMIC (see 11, 26)

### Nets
+1V375_CORE: R340.2
+1V375_SOC: C408.1 C409.1 C410.2 L12.2 R336.2
+3V0_ALWAYS: R405.2
+3V3_HDR: C429.1 C430.1 C431.1 C432.2 L13.2 R399.2 TP40.1
+VIN_4V2: C406.1 C407.1 C427.1 C428.1 R334.2 R335.2 R397.2 R398.2 R403.1 U30.1(VIN_1) U30.2(VDD) U30.16(VIN_2) U36.1(VIN_1) U36.2(VDD) U36.16(VIN_2)
GND: C406.2 C407.2 C408.2 C409.2 C427.2 C428.2 C429.2 C430.2 C431.2 R337.1 R338.1 R339.1 R342.1 R343.1 R344.1 R400.1 R401.1 R402.1 R406.1 R407.1 R408.1 U30.10(SGND) U30.11(PGND_1) U30.12(PGND_2) U30.17(EPAD) U36.10(SGND) U36.11(PGND_1) U36.12(PGND_2) U36.17(EPAD)
+PWRON_1V375_OPT: R341.2 ; port +PWRON_1V375_OPT
COMP_1V375: C411.2 R343.2 U30.8(COMP)
COMP_3V3_HDR: C433.2 R407.2 U36.8(COMP)
EN_1V375: R340.1 R341.1 U30.5(EN)
EN_3V3_HDR: R403.2 R404.1 U36.5(EN)
FB_1V375: C410.1 R336.1 R339.2 U30.9(FB)
FB_3V3_HDR: C432.1 R399.1 R402.2 U36.9(FB)
FS_1V375: R334.1 R337.2 U30.6(FS)
FS_3V3_HDR: R397.1 R400.2 U36.6(FS)
PHASE_1V375: L12.1 U30.13(PHASE_1) U30.14(PHASE_2) U30.15(PHASE_3)
PHASE_3V3_HDR: L13.1 U36.13(PHASE_1) U36.14(PHASE_2) U36.15(PHASE_3)
POK_1V375_OPT: U30.3(PG) ; port POK_1V375_OPT
POK_3V3_OPT: R405.1 U36.3(PG) ; port POK_3V3_OPT
POK_PMIC: R404.2 ; port POK_PMIC
SS_1V375: R342.2 U30.7(SS)
SS_3V3_HDR: R406.2 U36.7(SS)
SYNC_1V375: R335.1 R338.2 U30.4(SYNC)
SYNC_3V3_HDR: R398.1 R401.2 U36.4(SYNC)
NetC411_1: C411.1 R344.2
NetC433_1: C433.1 R408.2

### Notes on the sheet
- PWR +1V375_SOC OPT, +3V3 OPT
- Optional +1V375_SOC
- DESIGN NOTE:
  Fit this optional +1V375_SOC regulator to support iMX6DQP (the new iMX6 PLUS CPU), which requires higher current.
- DESIGN NOTE:
  In case this Optional +1V375_SOC is used fit U30, L12, C408 and C409.
  Be sure R351 is fitted, L8 and R384 not fitted.
- DESIGN NOTE:
  +1V375_SOC / max 4A / peak 5.2A
  (Required 3.4A)
- DESIGN NOTE:
  Rest of the output capacitors are placed on PMIC page.
- DESIGN NOTE:
  Default switching frequency 1MHz (FS tied to Vin). Use R337 to adjust the operating frequency.
- DESIGN NOTE:
  resistor values for output voltage 1V375:
  R336=R339*(Vout/Vref-1)=63.4k*(1.375/0.6-1)=81.892k
  backward control:
  Vout=Vref*(R336+R339)/R339=0.6*(82k+63.4k)/63.4k=1.376V
- DESIGN NOTE:
  Mode selection (SYNC):
  Vin - PWM mode
  GND - PFM mode
- DESIGN NOTE:
  If feedback loop needs to be compansated fit C410. Check out the loop analysis before its first used.
- DESIGN NOTE:
  If external compansation is used unfit R343, fit C411 and R344. Check out the loop analysis before its first used.
- DESIGN NOTE:
  To adjust the soft-start time (1ms when tied to GND) replace resistor R342 with a capacitor smaller than 33nF.
- Optional +3V3
- DESIGN NOTE:
  This Optional +3V3 regulator can deliver up to 4A to the board to board headers and can be used to supply number of add-on boards.
  In comparision, the PMIC can deliver only around 200mA to the headers, however using PMIC and not fitting Optional +3V3 can lower the board price.
- DESIGN NOTE:
  The higher inductor value can be selected if the testing shows that the performance can be improved.
- DESIGN NOTE:
  Default switching frequency 1MHz (FS tied to Vin). Use R400 to adjust the operating frequency.
- DESIGN NOTE:
  +3V3_HDR / max 4A / peak 5.2A
  (Required 3A)
- DESIGN NOTE:
  resistor values for output voltage 3V3:
  R339=R402*(Vout/Vref-1)=86.6k*(3.3/0.6-1)=389.7k
  backward control:
  Vout=Vref*(R339+R402)/R402=0.6*(86.6k+390k)/86.6k=3.302V
- DESIGN NOTE:
  +3V3_HDR source can be switched on by input power. In this case, the add-on board is supplied even if the main board is off or in sleep.
- DESIGN NOTE:
  If feedback loop needs to be compansated fit C432. Check out the loop analysis before its first used.
- DESIGN NOTE:
  To adjust the soft-start time (1ms when tied to GND) replace resistor R406 with a capacitor smaller than 33nF.
- DESIGN NOTE:
  If external compansation is used unfit R407, fit C433 and R408. Check out the loop analysis before its first used.
- FREE for personal and commercial use. See the license.
- Variant:
- Checked by
- Designed by www.fedevel.com

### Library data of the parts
C406 C407 C427 C428 = C1608X5R0J226M080AC: as C364 on sheet [26] - PWR PMIC
C408 C409 C429-C431 = GRM188R60G226MEA0L: as C352-C363 on sheet [26] - PWR PMIC
C410 C432 = C1005C0G1H220J: as C177-C179 on sheet [14] - MCU
C411 C433 = C1005X7R1H221K: CAP CER 220PF 50V X7R 10% 0402; Manufacturer: TDK Corporation; .Checked PCB: used
L12 L13 = IHLP2020BZER1R0M11: INDUCTOR POWER 1.0UH 7.5A SMD; Manufacturer: Vishay Dale; Type: Molded; Inductance: 1µH; Tolerance: ±20%; Current - Saturation: 7A; Shielding: Shielded; DC Resistance (DCR): 18.1 mOhm Max; Frequency - Self Resonant: 66MHz; Frequency - Test: 100kHz; .Checked PCB: MM
R334 R340-R343 R397 R404 R406 R407 = RC0402JR-070RL: as R204 on sheet [14] - MCU
R335 R398 R405 = RC0402FR-0710KL: as R270 on sheet [14] - MCU
R336 = RC0402FR-0782KL: RES 82.0K OHM 1/16W 1% 0402 SMD; Manufacturer: Yageo; Power (Watts): 0.063W, 1/16W; Temperature Coefficient: ±100ppm/°C; .Creator: MM
R337 R400 = RC0402FR-07150KL: RES 150K OHM 1/16W 1% 0402 SMD; Manufacturer: Yageo; Power (Watts): 0.063W, 1/16W; Temperature Coefficient: ±100ppm/°C; .Creator: MM
R338 R344 R401 R408 = RMCF0402FT100K: as R393-R396 on sheet [14] - MCU
R339 = CRCW040263K4FKED: RES SMD 63.4K OHM 1% 1/16W 0402; Manufacturer: Vishay Dale; Power (Watts): 0.063W, 1/16W; Temperature Coefficient: ±100ppm/°C; .Checked PCB: MM
R399 = CRCW0402390KFKED: RES 390K OHM 1/16W 1% 0402 SMD; Manufacturer: Vishay Dale; Power (Watts): 0.063W, 1/16W; Temperature Coefficient: ±100ppm/°C; .Creator: MM; .Checked SCH: used
R402 = RC0402FR-0786K6L: RES SMD 86.6K OHM 1% 1/16W 0402; Manufacturer: Yageo; Power (Watts): 0.063W, 1/16W; Temperature Coefficient: ±100ppm/°C; .Creator: MM
R403 = RC0402FR-0747KL: as R237 on sheet [26] - PWR PMIC
TP40 = TP_25MILC: Test Point 25mil
U30 U36 = ISL8024AIRTAJZ-T7A: IC REG BUCK SYNC ADJ 4A 16TQFN; Manufacturer: Intersil; Output Type: Adjustable; Number of Outputs: 1; Voltage - Output: 0.6 V ~ 5.5 V; Voltage - Input: 2.7 V ~ 5.5 V; Frequency - Switching: 490kHz ~ 4.2MHz; Synchronous Rectifier: Yes; .Creator: MM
